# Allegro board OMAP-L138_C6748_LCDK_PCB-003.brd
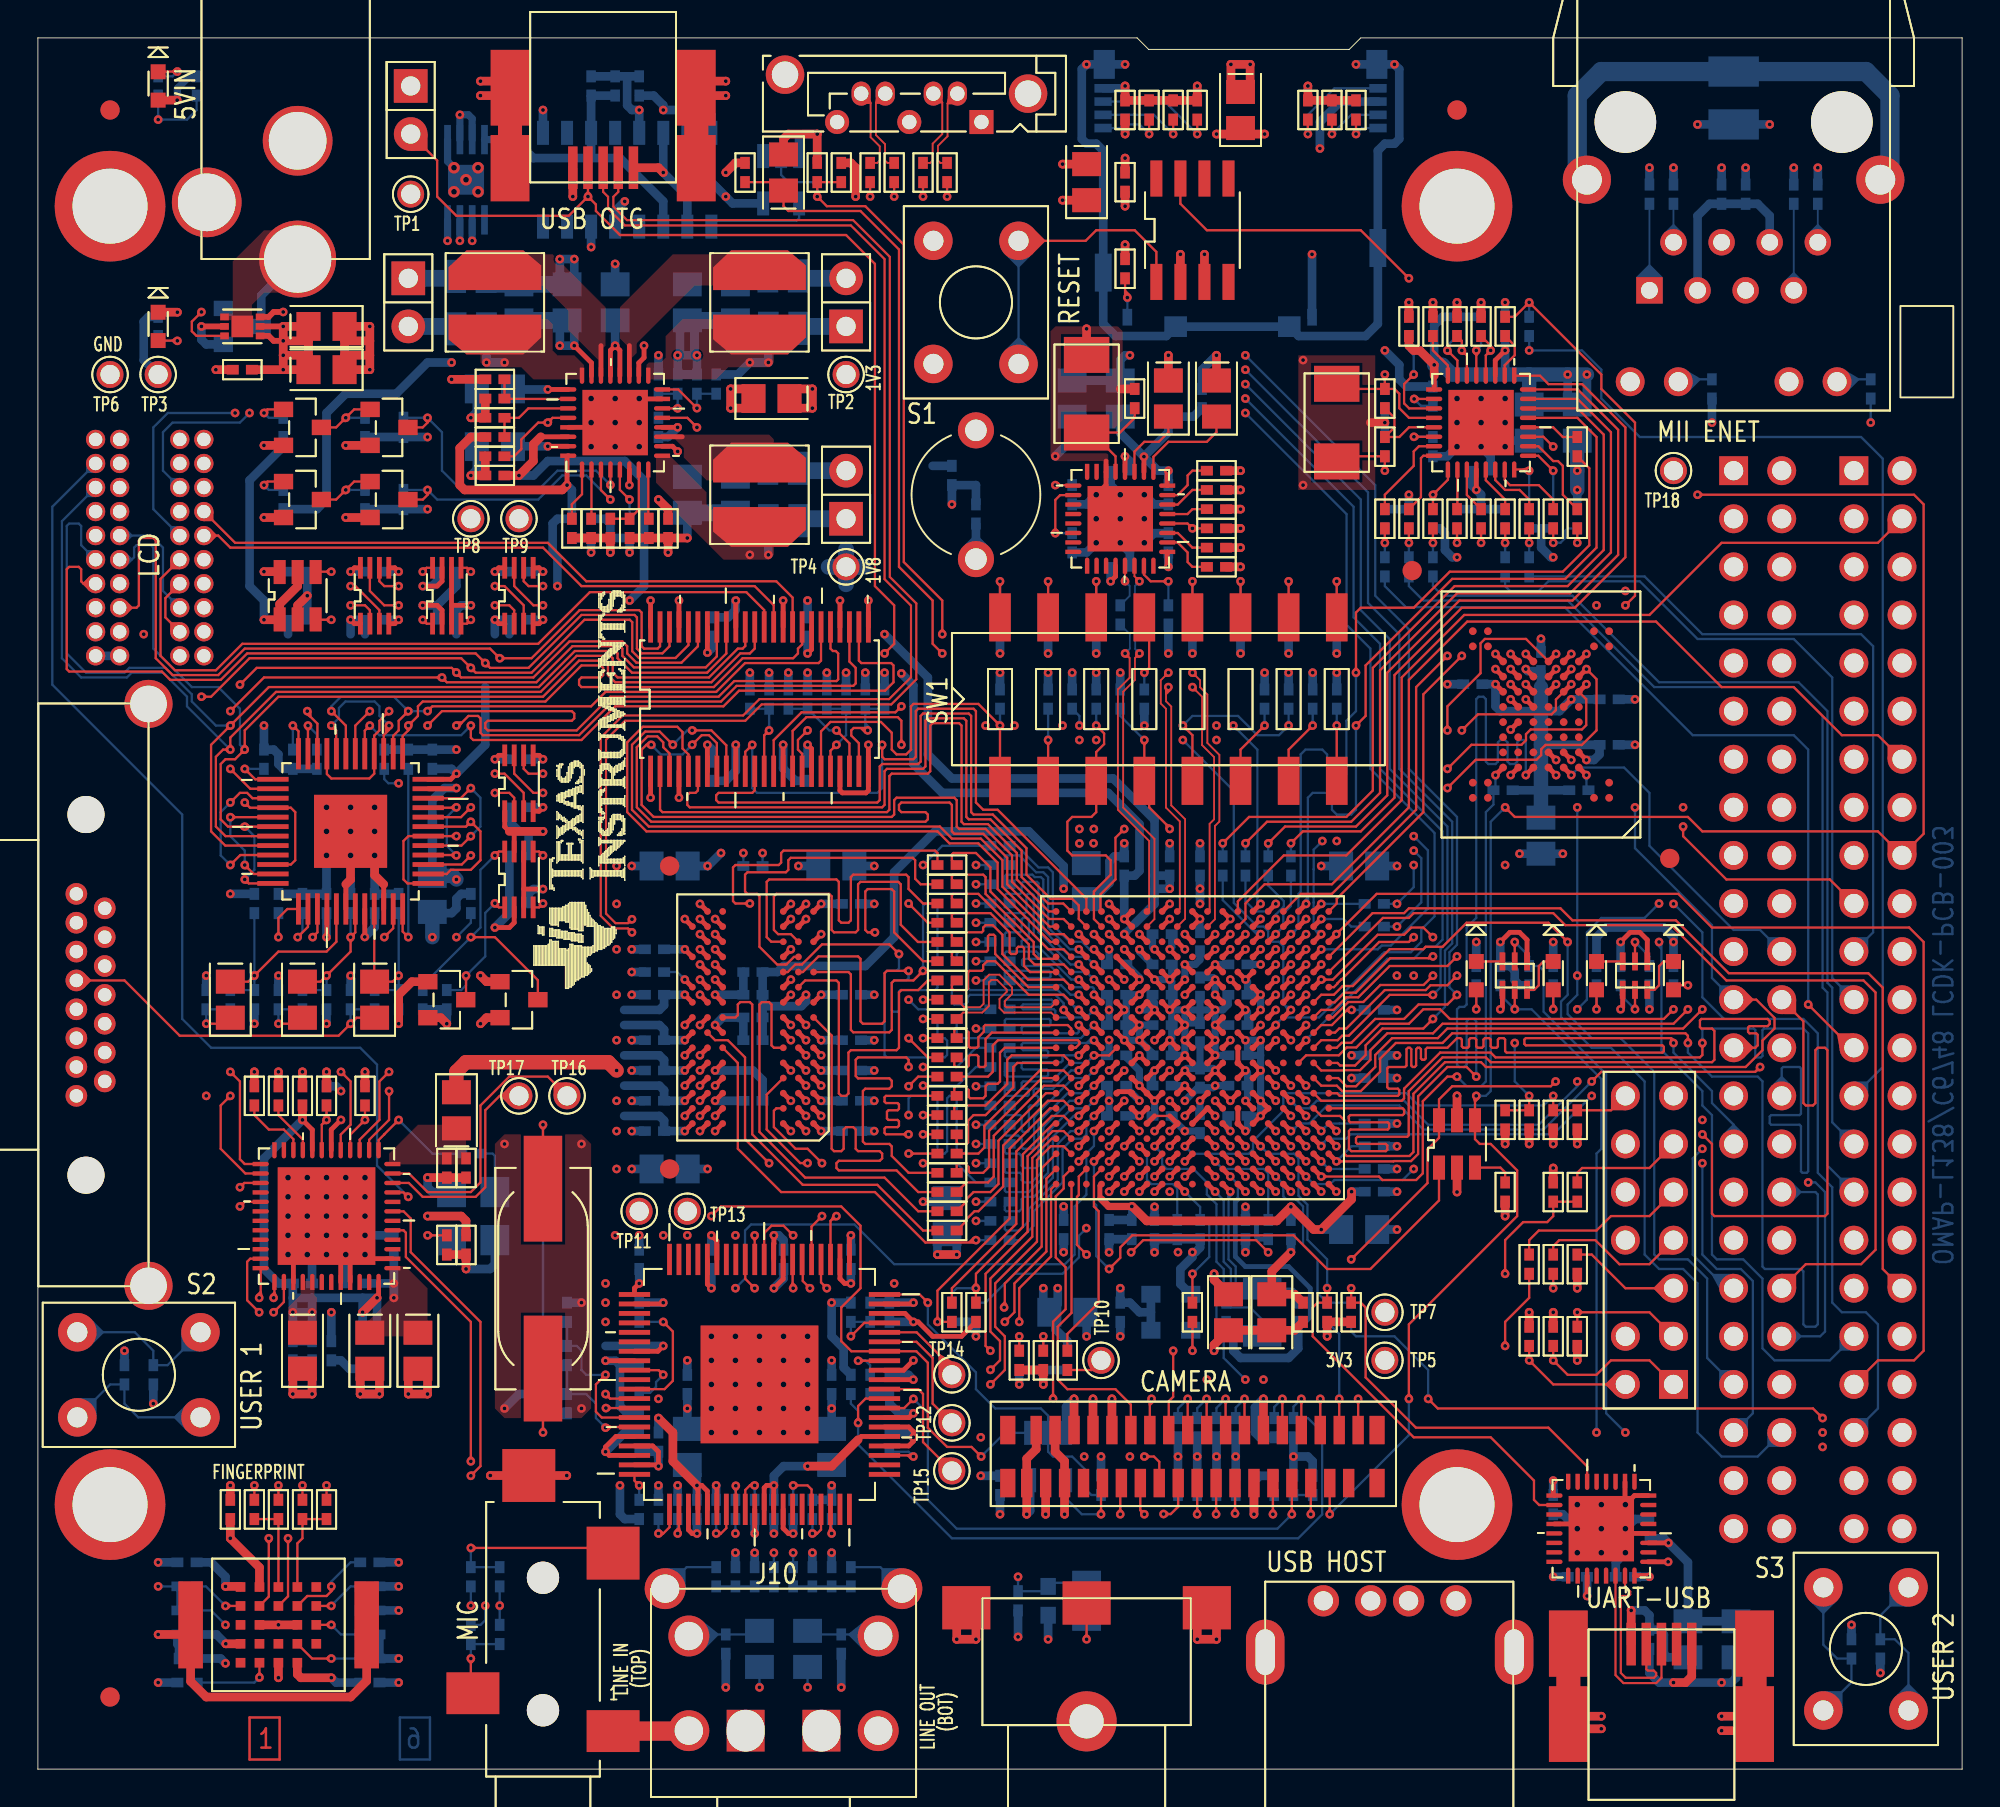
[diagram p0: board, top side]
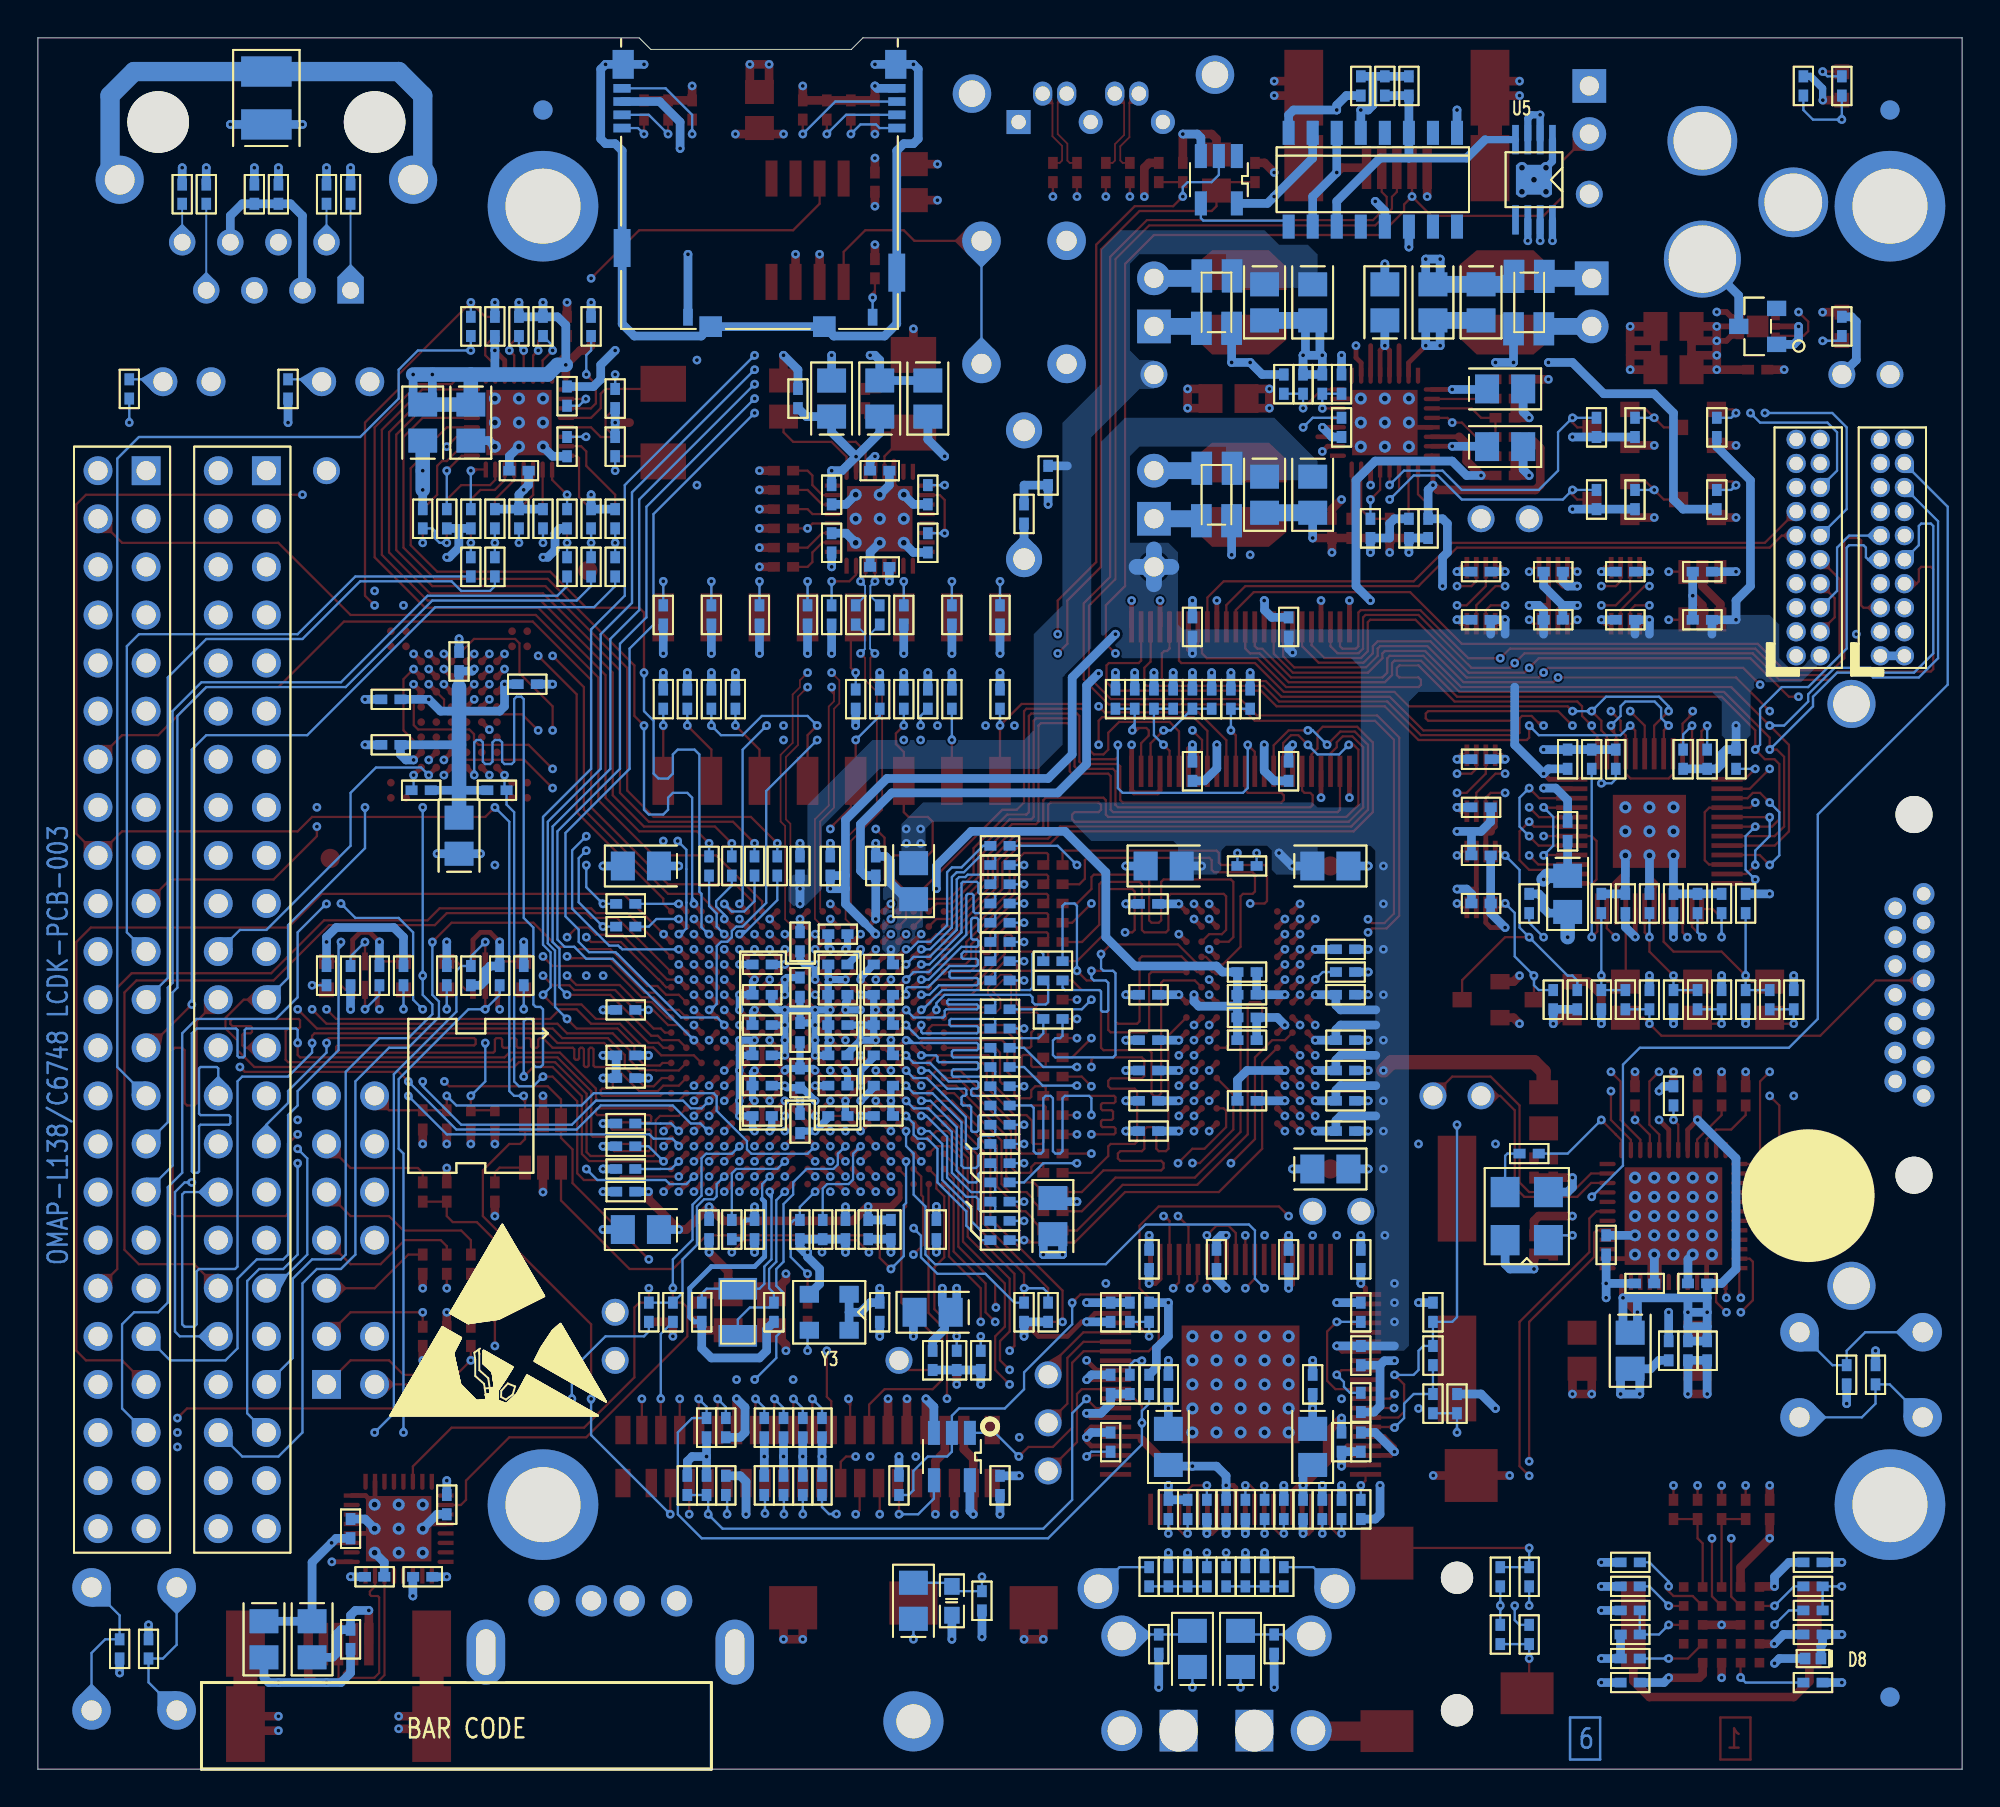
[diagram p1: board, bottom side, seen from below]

Outline 101.6 x 91.44 mm; copper layers: TOP, LYR2_GND, LYR3, LYR4, LYR5_PWR, BOTTOM. Coordinates in mm from the lower left corner of the outline.
Outline path: 0,91.44 0,0 101.6,0 101.6,91.44 69.85,91.44 69.24,90.83 58.65,90.83 58.04,91.44 0,91.44

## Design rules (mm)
net group RX: nets ENET_RXN ENET_RXP
net group SATA_REF_CLK: nets SATA_REF_CLKN SATA_REF_CLKP
net group SATA_REF_CLK_K: nets SATA_REF_CLKN_K SATA_REF_CLKP_K
net group SATA_RX: nets SATA_RXN SATA_RXP
net group SATA_RX_R: nets N27882474 N27882599
net group SATA_TX: nets SATA_TXN SATA_TXP
net group SATA_TX_R: nets N27881562 N27882349
net group TX: nets ENET_TXN ENET_TXP
net group USB0_D: nets USB0_DN USB0_DP
net group USB1_D: nets USB1_DN USB1_DP
net group USBD: nets USB_UART_DN USB_UART_DP
net group 1: nets ACTIVITYLED
net group 2: nets LAN_XTAL1 LAN_XTAL2 VCC_3V3A
net group CVIDEO: nets CVIDEO_DIN0 CVIDEO_DIN1 CVIDEO_DIN2 CVIDEO_DIN3 CVIDEO_DIN4 CVIDEO_DIN5 CVIDEO_DIN6 CVIDEO_DIN7
net group DDR_ADDR: nets DDR_A0 DDR_A1 DDR_A2 DDR_A3 DDR_A4 DDR_A5 DDR_A6 DDR_A7 DDR_A8 DDR_A9 DDR_A10 DDR_A11 DDR_A12 DDR_A13 DDR_BA0 DDR_BA1 DDR_BA2 DDR_CASN DDR_CKE DDR_CLKN DDR_CLKP DDR_CSN DDR_RASN DDR_WEN
net group DDR_ADDR_CPU: nets CPU_DDR_A0 CPU_DDR_A1 CPU_DDR_A2 CPU_DDR_A3 CPU_DDR_A4 CPU_DDR_A5 CPU_DDR_A6 CPU_DDR_A7 CPU_DDR_A8 CPU_DDR_A9 CPU_DDR_A10 CPU_DDR_A11 CPU_DDR_A12 CPU_DDR_A13 CPU_DDR_BA0 CPU_DDR_BA1 CPU_DDR_BA2 CPU_DDR_CASN CPU_DDR_CKE CPU_DDR_CLKN CPU_DDR_CLKP CPU_DDR_CSN CPU_DDR_RASN CPU_DDR_WEN
net group DDR_DATA: nets DDR_DQ0 DDR_DQ1 DDR_DQ2 DDR_DQ3 DDR_DQ4 DDR_DQ5 DDR_DQ6 DDR_DQ7 DDR_DQ8 DDR_DQ9 DDR_DQ10 DDR_DQ11 DDR_DQ12 DDR_DQ13 DDR_DQ14 DDR_DQ15 DDR_DQM0 DDR_DQM1 DDR_DQS0 DDR_DQS1
net group DDR_DATA_CPU: nets CPU_DDR_DQ0 CPU_DDR_DQ1 CPU_DDR_DQ2 CPU_DDR_DQ3 CPU_DDR_DQ4 CPU_DDR_DQ5 CPU_DDR_DQ6 CPU_DDR_DQ7 CPU_DDR_DQ8 CPU_DDR_DQ9 CPU_DDR_DQ10 CPU_DDR_DQ11 CPU_DDR_DQ12 CPU_DDR_DQ13 CPU_DDR_DQ14 CPU_DDR_DQ15 CPU_DDR_DQM0 CPU_DDR_DQM1 CPU_DDR_DQS0 CPU_DDR_DQS1
net group DOUT_LCD_D: nets VPIF_DOUT0/LCD_D_0 VPIF_DOUT1/LCD_D_1 VPIF_DOUT2/LCD_D_2 VPIF_DOUT3/LCD_D_3 VPIF_DOUT4/LCD_D_4 VPIF_DOUT5/LCD_D_5 VPIF_DOUT6/LCD_D_6 VPIF_DOUT7/LCD_D_7 VPIF_DOUT8/LCD_D_8 VPIF_DOUT9/LCD_D_9 VPIF_DOUT10/LCD_D_10 VPIF_DOUT11/LCD_D_11 VPIF_DOUT12/LCD_D_12 VPIF_DOUT13/LCD_D_13 VPIF_DOUT14/LCD_D_14 VPIF_DOUT15/LCD_D_15
net group EMA_A: nets EMA_A0 EMA_A1 EMA_A2 EMA_A3 EMA_A4 EMA_A5 EMA_A6 EMA_A7 EMA_A8 EMA_A9 EMA_A10 EMA_A11 EMA_A12 EMA_BA_0 EMA_BA_1 EMA_CLK EMA_CSN_2 EMA_CSN_3 EMA_CSN_4 EMA_CSN_5
net group EMA_D: nets EMA_D0 EMA_D1 EMA_D2 EMA_D3 EMA_D4 EMA_D5 EMA_D6 EMA_D7 EMA_D8 EMA_D9 EMA_D10 EMA_D11 EMA_D12 EMA_D13 EMA_D14 EMA_D15
net group LCD_D: nets LCD_1V8_D_0 LCD_1V8_D_1 LCD_1V8_D_2 LCD_1V8_D_3 LCD_1V8_D_4 LCD_1V8_D_5 LCD_1V8_D_6 LCD_1V8_D_7 LCD_1V8_D_8 LCD_1V8_D_9 LCD_1V8_D_10 LCD_1V8_D_11 LCD_1V8_D_12 LCD_1V8_D_13 LCD_1V8_D_14 LCD_1V8_D_15
net group MII: nets AXR0/ECAP0_APWM0/MII_TXD0 AXR1/MII_TXD1 AXR2/MII_TXD2 AXR3/MII_TXD3 AXR4/MII_COL AXR5/MII_TXCLK AXR6/MII_TXEN
net group MMCSD0: nets MMCSD0_CLK MMCSD0_CMD MMCSD0_D0 MMCSD0_D1 MMCSD0_D2 MMCSD0_D3 MMCSD0_D4 MMCSD0_D6 MMCSD0_D7

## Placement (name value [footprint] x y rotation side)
BH1  BATTERY Hl, DNI  [BATTERY]  49.53 67.31 90 top
C1  10uF/16V X5R  [0805]  15.24 76.2 0 top
C2  10uF/16V X5R  [0805]  15.24 73.91 0 top
C3  0.1uF/50V X7R  [0402]  10.79 73.91 180 top
C4  0.1uF/50V X7R  [0402]  57.4 83.82 270 top
C5  10uF/16V X5R  [0805]  36.83 67.31 270 bottom
C6  10uF/16V X5R  [0805]  34.29 67.31 270 bottom
C7  1uF/16V X7R  [0402]  33.27 65.53 270 top
C8  10uF/16V X5R  [0805]  24.13 69.85 180 bottom
C9  10uF/16V X5R  [0805]  24.13 72.9 180 bottom
C10  10uF/16V X5R  [0805]  30.48 77.47 90 bottom
C11  10uF/16V X5R  [0805]  34.29 77.47 270 bottom
C12  10uF/16V X5R  [0805]  36.83 77.47 270 bottom
C13  10uF/16V X5R  [0805]  27.94 77.47 270 bottom
C14  10uF/16V X5R  [0805]  25.4 77.47 270 bottom
C15  2.2uF/16V X7R  [0402]  24.13 69.34 180 top
C16  2.2uF/16V X7R  [0402]  24.13 68.33 0 top
C17  2.2uF/16V X7R  [0402]  28.19 65.53 270 bottom
C18  1uF/16V X7R  [0402]  29.21 65.53 270 bottom
C19  0.1uF/50V X7R  [0402]  30.48 88.9 90 bottom
C20  0.1uF/50V X7R  [0402]  80.01 13.97 270 bottom
C21  0.1uF/50V X7R  [0402]  83.82 10.16 180 bottom
C22  10uF/16V X5R  [0805]  89.66 6.86 270 bottom
C23  0.1uF/50V X7R  [0402]  85.09 12.7 90 bottom
C24  0.1uF/50V X7R  [0402]  85.09 6.86 270 bottom
C25  0.22uF/50V X7R  [0402]  60.16 28.5 270 bottom
C26  0.22uF/50V X7R  [0402]  54.61 56.52 90 bottom
C27  0.1uF/50V X7R  [0402]  59.69 67.31 270 bottom
C28  0.1uF/50V X7R  [0402]  59.69 64.77 90 bottom
C29  0.1uF/50V X7R  [0402]  61.47 72.39 90 bottom
C30  10uF/16V X5R  [0805]  59.69 72.39 90 bottom
C31  0.1uF/50V X7R  [0402]  57.15 68.58 180 bottom
C32  0.1uF/50V X7R  [0402]  57.15 63.5 0 bottom
C33  10uF/16V X5R  [0805]  54.61 72.39 270 bottom
C34  0.01uF/50V X7R  [0402]  58.42 60.96 270 bottom
C35  0.1uF/50V X7R  [0402]  56.96 40.9 180 bottom
C36  0.1uF/50V X7R  [0402]  56.96 36.1 180 bottom
C37  0.1uF/50V X7R  [0402]  56.96 39.3 180 bottom
C38  0.1uF/50V X7R  [0402]  59.36 39.3 0 bottom
C39  0.1uF/50V X7R  [0402]  59.36 37.7 0 bottom
C40  0.1uF/50V X7R  [0402]  61.36 43.7 90 bottom
C41  0.1uF/50V X7R  [0402]  61.36 34.1 270 bottom
C42  0.1uF/50V X7R  [0402]  54.36 21.59 270 bottom
C43  0.1uF/50V X7R  [0402]  54.16 28.5 90 bottom
C44  0.1uF/50V X7R  [0402]  63.36 36.1 180 bottom
C45  10uF/16V X5R  [0805]  54.36 24.13 0 bottom
C46  0.01uF/50V X7R  [0402]  57.15 60.96 270 bottom
C47  10pF/50V NPO  [0402]  57.91 72.39 90 top
C48  10uF/16V X5R  [0805]  62.23 72.39 270 top
C49  10uF/16V X5R  [0805]  59.69 72.39 270 top
C50  0.1uF/50V X7R  [0402]  63.76 28.5 270 bottom
C51  0.1uF/50V X7R  [0402]  56.96 42.5 180 bottom
C52  0.1uF/50V X7R  [0402]  56.96 37.7 180 bottom
C53  0.1uF/50V X7R  [0402]  59.36 36.1 180 bottom
C54  0.1uF/50V X7R  [0402]  58.96 28.5 270 bottom
C55  0.1uF/50V X7R  [0402]  59.36 34.5 0 bottom
C56  0.1uF/50V X7R  [0402]  70.56 36.5 0 bottom
C57  0.1uF/50V X7R  [0402]  63.36 40.9 180 bottom
C58  0.1uF/50V X7R  [0402]  63.36 42.5 0 bottom
C59  0.1uF/50V X7R  [0402]  59.36 44.1 180 bottom
C60  0.1uF/50V X7R  [0402]  70.56 37.7 0 bottom
C61  0.1uF/50V X7R  [0402]  63.36 34.5 180 bottom
C62  0.1uF/50V X7R  [0402]  63.36 37.7 180 bottom
C63  10uF/16V X5R  [0805]  69.76 47.7 0 bottom
C64  0.1uF/50V X7R  [0402]  59.76 47.7 90 bottom
C65  0.1uF/50V X7R  [0402]  56.96 34.5 180 bottom
C66  0.1uF/50V X7R  [0402]  66.8 24.13 90 top
C67  0.1uF/50V X7R  [0402]  59.36 42.5 0 bottom
C68  0.1uF/50V X7R  [0402]  57.36 47.7 90 bottom
C69  10uF/16V X5R  [0805]  65.15 24.13 90 top
C70  0.1uF/50V X7R  [0402]  56.56 28.5 270 bottom
C71  0.1uF/50V X7R  [0402]  66.16 28.5 270 bottom
C72  0.1uF/50V X7R  [0402]  61.36 47.7 90 bottom
C73  0.1uF/50V X7R  [0402]  57.76 28.5 270 bottom
C74  0.1uF/50V X7R  [0402]  61.36 41.3 270 bottom
C75  0.1uF/50V X7R  [0402]  61.36 38.9 90 bottom
C76  0.1uF/50V X7R  [0402]  70.56 30.5 0 bottom
C77  0.1uF/50V X7R  [0402]  61.36 36.5 270 bottom
C78  0.1uF/50V X7R  [0402]  63.36 39.3 180 bottom
C79  0.1uF/50V X7R  [0402]  59.36 40.9 0 bottom
C80  10uF/16V X5R  [0805]  69.76 28.5 0 bottom
C81  10uF/16V X5R  [0805]  55.37 83.82 270 top
C82  0.1uF/50V X7R  [0402]  57.4 87.63 270 top
C83  10uF/16V X5R  [0805]  39.37 84.33 90 top
C84  22pF/50V NPO  [0402]  66.55 24.13 270 bottom
C85  22pF/50V NPO  [0402]  62.74 24.13 270 bottom
C86  0.1uF/50V X7R  [0402]  57.15 24.13 270 bottom
C90  0.01uF/50V X7R  [0402]  46.74 84.33 90 top
C91  0.01uF/50V X7R  [0402]  48.01 84.33 90 top
C92  0.01uF/50V X7R  [0402]  45.21 84.33 90 top
C93  0.01uF/50V X7R  [0402]  43.94 84.33 90 top
C94  0.1uF/50V X7R  [0402]  17.78 60.71 0 bottom
C95  0.1uF/50V X7R  [0402]  17.78 63.25 180 bottom
C96  0.1uF/50V X7R  [0402]  20.83 49.53 270 bottom
C97  0.1uF/50V X7R  [0402]  17.78 45.72 270 bottom
C98  1uF/16V X7R  [0402]  15.24 45.72 90 bottom
C99  0.1uF/50V X7R  [0402]  35.56 52.7 90 bottom
C100  0.1uF/50V X7R  [0402]  40.64 52.7 90 bottom
C101  0.1uF/50V X7R  [0402]  35.56 60.33 270 bottom
C102  0.1uF/50V X7R  [0402]  40.64 60.33 270 bottom
C103  0.1uF/50V X7R  [0402]  20.83 53.34 270 bottom
C104  0.1uF/50V X7R  [0402]  25.4 50.8 0 bottom
C105  33pF/50V NPO  [0402]  10.16 40.64 90 bottom
C106  0.1uF/50V X7R  [0402]  25.4 53.34 180 bottom
C107  0.1uF/50V X7R  [0402]  22.86 45.72 270 bottom
C108  100pF/50V NPO  [0402]  11.43 40.64 90 bottom
C109  270pF/50V NPO  [0402]  8.89 40.64 270 bottom
C110  33pF/50V NPO  [0402]  13.97 40.64 90 bottom
C111  100pF/50V NPO  [0402]  15.24 40.64 90 bottom
C112  270pF/50V NPO  [0402]  12.7 40.64 270 bottom
C113  33pF/50V NPO  [0402]  17.78 40.64 90 bottom
C114  100pF/50V NPO  [0402]  19.05 40.64 90 bottom
C115  270pF/50V NPO  [0402]  16.51 40.64 270 bottom
C116  0.1uF/50V X7R  [0402]  12.7 45.72 270 bottom
C118  0.1uF/50V X7R  [0402]  25.4 45.72 180 bottom
C119  0.1uF/50V X7R  [0402]  37.76 39.7 180 bottom
C120  0.01uF/50V X7R  [0402]  32.56 43.3 180 bottom
C121  0.1uF/50V X7R  [0402]  32.56 40.9 180 bottom
C122  0.01uF/50V X7R  [0402]  32.56 38.5 180 bottom
C123  10uF/16V X5R  [0805]  33.36 31.7 180 bottom
C124  10uF/16V X5R  [0805]  33.36 47.7 180 bottom
C125  0.1uF/50V X7R  [0402]  32.56 36.9 180 bottom
C126  0.01uF/50V X7R  [0402]  32.56 35.3 180 bottom
C127  0.1uF/50V X7R  [0402]  32.56 33.7 180 bottom
C128  0.01uF/50V X7R  [0402]  42.96 45.7 0 bottom
C129  0.1uF/50V X7R  [0402]  42.96 40.9 0 bottom
C130  0.01uF/50V X7R  [0402]  42.96 38.5 0 bottom
C131  10uF/16V X5R  [0805]  42.16 47.7 0 bottom
C132  0.1uF/50V X7R  [0402]  42.96 36.9 0 bottom
C133  0.01uF/50V X7R  [0402]  42.96 35.3 0 bottom
C134  0.1uF/50V X7R  [0402]  42.96 33.7 0 bottom
C135  0.01uF/50V X7R  [0402]  37.76 35.3 0 bottom
C136  0.1uF/50V X7R  [0402]  37.76 42.1 0 bottom
C137  10pF, DNI  [0402]  92.71 83.19 90 bottom
C138  0.1uF/50V X7R  [0402]  75.76 57.3 180 bottom
C139  0.1uF/50V X7R  [0402]  79.36 58.5 90 bottom
C140  0.01uF/50V X7R  [0402]  82.96 54.1 0 bottom
C141  0.1uF/50V X7R  [0402]  25.4 48.26 180 bottom
C142  22pF/50V NPO  [0402]  27.94 24.13 90 bottom
C143  22pF/50V NPO  [0402]  26.67 19.3 90 bottom
C144  1uF/16V X7R  [0402]  73.66 69.85 270 bottom
C145  1uF/16V X7R  [0402]  82.96 56.5 0 bottom
C146  0.1uF/50V X7R  [0402]  34.29 20.32 90 bottom
C147  0.1uF/50V X7R  [0402]  32.77 17.27 270 bottom
C148  0.1uF/50V X7R  [0402]  34.8 13.72 270 bottom
C149  0.1uF/50V X7R  [0402]  31.75 26.92 90 bottom
C150  0.1uF/50V X7R  [0402]  39.37 26.92 90 bottom
C151  0.1uF/50V X7R  [0402]  44.96 24.13 90 bottom
C152  0.1uF/50V X7R  [0402]  35.56 26.92 270 bottom
C153  0.1uF/50V X7R  [0402]  42.93 26.92 270 bottom
C154  0.1uF/50V X7R  [0402]  31.75 21.84 270 bottom
C155  0.1uF/50V X7R  [0402]  44.96 20.32 270 bottom
C156  0.1uF/50V X7R  [0402]  41.91 20.32 90 bottom
C157  0.1uF/50V X7R  [0402]  31.75 17.27 270 bottom
C158  0.1uF/50V X7R  [0402]  38.86 13.72 270 bottom
C159  0.1uF/50V X7R  [0402]  31.75 13.72 270 bottom
C160  0.1uF/50V X7R  [0402]  32.77 13.72 90 bottom
C161  0.1uF/50V X7R  [0402]  33.78 13.72 90 bottom
C162  0.1uF/50V X7R  [0402]  36.83 13.72 90 bottom
C163  330pF/100V X7R  [0603]  53.34 8.89 270 bottom
C164  0.1uF/50V X7R  [0402]  35.81 13.72 90 bottom
C165  0.1uF/50V X7R  [0402]  37.85 13.72 270 bottom
C166  0.1uF/50V X7R  [0402]  39.88 13.72 270 bottom
C167  0.1uF/50V X7R  [0402]  40.89 13.72 90 bottom
C168  0.1uF/50V X7R  [0402]  41.91 13.72 90 bottom
C169  0.1uF/50V X7R  [0402]  44.96 17.27 90 bottom
C170  10uF/16V X5R  [0805]  55.36 46.9 270 bottom
C171  10uF/16V X5R  [0805]  48.01 29.21 90 bottom
C172  0.1uF/50V X7R  [0402]  38.86 10.16 90 bottom
C173  0.47uF/50V X7R  [0402]  22.86 7.11 270 bottom
C174  220pF/50V NPO  [0402]  37.85 10.16 270 bottom
C175  0.47uF/50V X7R  [0402]  22.86 10.16 90 bottom
C176  0.1uF/50V X7R  [0402]  39.88 10.16 90 bottom
C177  220pF/50V NPO  [0402]  40.89 10.16 270 bottom
C178  10uF/16V X5R  [0805]  40.64 6.35 90 bottom
C179  10uF/16V X5R  [0805]  38.1 6.35 90 bottom
C180  0.1uF/50V X7R  [0402]  22.61 27.69 90 top
C181  1uF/16V X7R  [0402]  21.59 31.75 270 top
C182  0.1uF/50V X7R  [0402]  18.8 27.69 90 bottom
C183  0.1uF/50V X7R  [0402]  16.76 25.65 180 bottom
C184  10uF/16V X5R  [0805]  20.07 22.1 270 top
C185  0.1uF/50V X7R  [0402]  15.49 22.1 90 bottom
C186  0.1uF/50V X7R  [0402]  22.61 31.75 270 top
C187  0.1uF/50V X7R  [0402]  13.97 25.65 0 bottom
C188  0.1uF/50V X7R  [0402]  14.48 22.1 270 bottom
C189  0.1uF/50V X7R  [0402]  13.46 22.1 270 bottom
C190  0.1uF/50V X7R  [0402]  13.97 35.56 90 top
C191  10uF/16V X5R  [0805]  13.97 22.1 270 top
C193  0.1uF/50V X7R  [0402]  76.2 68.58 0 bottom
C194  10pF, DNI  [0402]  93.98 83.19 90 bottom
C196  10pF, DNI  [0402]  86.36 83.19 90 bottom
C197  10pF, DNI  [0402]  85.09 83.19 90 bottom
C198  0.022uF,10V  [0402]  90.17 83.19 90 bottom
C199  10uF/16V X5R  [0805]  78.74 71.12 270 bottom
C200  0.1uF/50V X7R  [0402]  77.47 76.2 90 bottom
C201  0.1uF/50V X7R  [0402]  72.39 76.2 90 top
C202  33pF/50V NPO  [0402]  71.12 69.85 270 bottom
C203  33pF/50V NPO  [0402]  71.12 72.39 90 bottom
C204  0.1uF/50V X7R  [0402]  25.4 60.71 0 bottom
C205  0.1uF/50V X7R  [0402]  25.4 63.25 180 bottom
C206  0.1uF/50V X7R  [0402]  21.59 63.25 180 bottom
C207  0.47uF/50V X7R  [0402]  10.16 13.72 270 top
C208  0.47uF/50V X7R  [0402]  17.53 4.57 180 bottom
C209  0.47uF/50V X7R  [0402]  7.87 10.92 0 bottom
C210  0.1uF/50V X7R  [0402]  21.59 60.71 180 bottom
C211  0.47uF/50V X7R  [0402]  17.53 9.65 180 bottom
C212  0.47uF/50V X7R  [0402]  17.53 10.92 180 bottom
C213  0.47uF/50V X7R  [0402]  17.53 5.84 180 bottom
C214  0.47uF/50V X7R  [0402]  7.87 4.57 0 bottom
C215  0.1uF/50V X7R  [0402]  50.8 14.99 90 bottom
C216  0.1uF/50V X7R  [0402]  13.72 60.71 180 bottom
C217  0.1uF/50V X7R  [0402]  13.72 63.25 0 bottom
D1  BZX84B5V1LT1G  [SOT23_3]  10.79 76.2 90 bottom
D2  LED  [LED2-31SQ]  6.35 88.9 270 top
D3  LED  [LED2-31SQ]  6.35 76.2 270 top
D4  LED  [LED2-31SQ]  75.95 41.91 270 top
D5  LED  [LED2-31SQ]  80.01 41.91 270 top
D6  LED  [LED2-31SQ]  82.3 41.91 270 top
D7  LED  [LED2-31SQ]  86.36 41.91 270 top
D8  CP64004T  [DO1006]  7.87 5.84 180 bottom
DN1  BAV99LT1  [SOT23_3]  21.59 40.64 270 top
DN2  BAV99LT1  [SOT23_3]  25.4 40.64 270 top
FB1  MMZ2012S121A  [0805]  38.73 72.39 180 top
FB2  MMZ2012S121A  [0805]  87.12 6.86 270 bottom
FB3  MMZ2012S121A  [0805]  57.15 72.39 90 bottom
FB4  MMZ2012S121A  [0805]  62.87 24.13 90 top
FB5  MMZ2012S121A  [0805]  63.5 87.63 270 top
FB6  MMZ2012S121A  [0805]  20.83 46.23 270 bottom
FB8  MMZ2012S121A  [0805]  79.36 49.3 90 bottom
FB9  MMZ2012S121A  [0805]  34.29 17.02 270 bottom
FB10  MMZ2012S121A  [0805]  41.91 17.02 270 bottom
FB11  MMZ2012S121A  [0805]  55.37 8.89 90 bottom
FB14  MMZ2012S121A  [0805]  17.53 22.1 270 top
FB15  MMZ2012S121A  [0805]  22.1 34.8 90 top
FB16  MMZ2012S121A  [0805]  17.53 22.1 270 bottom
FB18  MMZ2012S121A  [0805]  81.28 71.12 90 bottom
J1  Power Jack RAPC712  [RAPC712]  13.72 79.76 270 top
J2  56579-0576  [USB5MINI_4SHIELDED_SMD-4]  29.84 84.58 270 top
J3  56579-0576  [USB5MINI_4SHIELDED_SMD-4]  85.72 6.6 90 top
J4  SCHA5B0200  [SD-MICRO-SCHA5B0300]  63.5 86.68 0 bottom
J5  USB-A Conn. - 87520-xx1xx  [USB_A_SH]  67.87 8.89 0 top
J6  72454-014LF  [CON2X100P-14_V6]  85.09 27.94 90 top
J7  SD-67491-002  [SATA]  41.91 87 0 top
J8  070213FR  [DB15F_60-59LS]  2.54 40.89 90 top
J9  RCJ-014  [RCA4SMD_11X15MM]  55.37 2.52 180 top
J10  SJD-3510-33  [JACK6_551X433_STACK]  39.37 2.03 180 top
J11  STX-3500-4NTR  [STX3500]  26.67 6.86 90 top
J13  ETHER  [RJ45-2LED]  85.09 78.11 90 top
J14  CONN_PCB_23x2-S  [HEADER23X2]  89.53 68.58 270 top
J15  CONN_PCB_23x2-S  [HEADER23X2]  95.89 68.58 270 top
J16  52559-3652  [CON36UPSMD_P5MM]  60.96 16.51 180 top
JP1  HEADER 2  [HEADER_2X1]  19.68 88.9 180 top
JP2  HEADER 2  [HEADER_2X1]  42.67 66.04 0 top
JP3  HEADER 2  [HEADER_2X1]  19.56 78.74 180 top
JP4  HEADER 2  [HEADER_2X1]  42.67 76.2 0 top
L1  2.2uH/1.7A  [IND3P4SMD_5SQ]  38.1 67.31 270 top
L2  3.3uH/2.6A  [IND3P4SMD_5SQ]  24.13 77.47 90 top
L3  2.2uH/1.7A  [IND3P4SMD_5SQ]  38.1 77.47 270 top
L4  1uH/80mA  [0805]  10.16 40.64 270 top
L5  1uH/80mA  [0805]  13.97 40.64 270 top
L6  1uH/80mA  [0805]  17.78 40.64 270 top
NOREF  -  []  0 0 0 top
NOREF#2  -  []  0 0 0 top
NOREF#3  -  []  74.93 13.97 0 top
NOREF#4  -  []  69.85 91.44 0 top
NOREF#5  -  []  0 -15.09 0 top
NOREF#6  -  []  -303.34 -250.06 0 top
NOREF#7  -  []  -14.07 0 90 top
NOREF#8  -  []  3.81 82.55 0 top
NOREF#9  -  [unnamed#2]  74.93 87.63 0 top
NOREF#10  -  []  0 91.44 0 top
NOREF#11  -  [unnamed#2]  3.81 3.81 0 top
NOREF#12  -  [unnamed#2]  3.81 82.55 0 top
NOREF#13  -  [unnamed#2]  74.93 13.97 0 top
NOREF#14  -  []  3.81 13.97 0 top
NOREF#15  -  [unnamed#2]  3.81 87.63 0 top
NOREF#16  -  [unnamed#2]  3.81 13.97 0 top
NOREF#17  -  []  3.81 13.97 0 top
NOREF#18  -  []  58.65 90.83 0 top
NOREF#19  -  []  101.6 0 0 top
NOREF#20  -  []  58.65 90.83 0 top
NOREF#21  -  []  58.04 91.44 0 top
NOREF#22  -  [unnamed#2]  74.93 82.55 0 top
NOREF#23  -  []  69.24 90.83 0 top
NOREF#24  -  []  70.11 26.07 180 bottom
NOREF#25  -  [unnamed#2]  74.93 87.63 180 bottom
NOREF#26  -  [unnamed#2]  3.81 87.63 180 bottom
NOREF#27  -  [unnamed#2]  3.81 3.81 180 bottom
NOREF#28  -  []  87.12 3.05 180 bottom
P1  HEADER_10X2  [CONN2X10_4028]  4.32 58.8 90 top
P2  HEADER_10X2  [CONN2X10_4028]  8.76 58.8 90 top
Q1  MMBT3904LT1G  [SOT23_3]  18.54 67.06 270 top
Q2  MMBT3904LT1G  [SOT23_3]  18.54 70.87 270 top
Q3  MMBT3904LT1G  [SOT23_3]  13.97 67.06 270 top
Q4  MMBT3904LT1G  [SOT23_3]  13.97 70.87 270 top
Q5  DMC56404  [SMINI6-F3-B]  84.33 41.91 180 top
Q6  DMC56404  [SMINI6-F3-B]  77.98 41.91 180 top
R1  510E/5% 1/10W  [0402]  6.35 88.9 90 bottom
R2  0.05ohm1% Sense  [1206_4PIN]  39.37 67.31 90 bottom
R3  1E/5%/1/10W  [0402]  32.77 70.87 90 bottom
R4  0.05ohm1% Sense  [1206_4PIN]  22.86 77.47 270 bottom
R5  0.05ohm1% Sense  [1206_4PIN]  39.37 77.47 90 bottom
R6  576K/1% 1/10W  [0402]  35.81 73.15 90 bottom
R7  4.7K/5% 1/10W  [0402]  32.26 65.53 270 top
R8  499K/1% 1/10W  [0402]  34.8 73.15 90 bottom
R9  330E/1% 1/10W  [0402]  6.35 76.2 270 bottom
R10  4.7K/5% 1/10W  [0402]  29.21 65.53 270 top
R11  4.7K/5% 1/10W  [0402]  28.19 65.53 270 top
R12  5.6K/1% 1/10W  [0402]  32.77 73.15 90 bottom
R13  0E  [0402]  30.23 65.53 270 top
R14  1.4K/1% 1/10W  [0402]  33.78 73.15 270 bottom
R15  4.7K/5% 1/10W  [0402]  31.24 65.53 90 bottom
R16  OR, DNI  [0402]  31.24 65.53 90 top
R17  200K/1% 1/10W  [0402]  24.13 72.39 0 top
R18  160K/1% 1/10W  [0402]  24.13 73.41 180 top
R19  300K/1% 1/10W  [0402]  24.13 71.37 0 top
R20  60K/1% 1/10W  [0402]  24.13 70.36 0 top
R21  4.7K/5% 1/10W  [0402]  31.75 88.9 90 bottom
R22  4.7K/5% 1/10W  [0402]  19.3 67.06 270 bottom
R23  4.7K/5% 1/10W  [0402]  19.3 70.87 270 bottom
R24  4.7K/5% 1/10W  [0402]  17.27 67.06 270 bottom
R25  4.7K/5% 1/10W  [0402]  29.21 88.9 90 bottom
R26  4.7K/5% 1/10W  [0402]  17.27 70.87 270 bottom
R27  1K/1% 1/10W  [0402]  12.95 67.06 90 bottom
R28  1K/1% 1/10W  [0402]  12.95 70.87 90 bottom
R29  0E/5% 1/10W  [0402]  48.26 68.33 270 bottom
R30  10K, 5%  [0402]  81.28 10.16 0 bottom
R31  0, DNI  [0402]  49.53 66.29 270 bottom
R33  49.9E/1% 1/10W  [0402]  49.53 24.13 270 bottom
R34  4.7K/5% 1/10W  [0402]  62.23 64.52 180 top
R35  4.7K/5% 1/10W  [0402]  62.23 66.55 180 top
R36  4.7K/5% 1/10W  [0402]  62.23 68.58 180 top
R37  4.7K/5% 1/10W  [0402]  54.61 64.77 270 bottom
R38  4.7K/5% 1/10W  [0402]  54.61 67.31 270 bottom
R39  4.7K/5% 1/10W  [0402]  62.23 67.56 0 top
R40  4.7K/5% 1/10W  [0402]  62.23 63.5 0 top
R41  10K/1% 1/10W  [0402]  62.23 65.53 0 top
R42  10K, DNI  [0402]  59.69 60.96 270 bottom
R43  180, 1%  [0402]  60.96 24.13 90 top
R44  10K/5% 1/10W  [0402]  57.4 79.25 270 top
R45  10K/5% 1/10W  [0402]  58.67 87.63 270 top
R46  10K/5% 1/10W  [0402]  61.21 87.63 270 top
R47  10K/5% 1/10W  [0402]  67.06 87.63 270 top
R48  10K/5% 1/10W  [0402]  68.33 87.63 270 top
R49  10K/5% 1/10W  [0402]  69.6 87.63 270 top
R50  10K/5% 1/10W  [0402]  59.94 87.63 270 top
R51  10K, DNI  [0402]  42.42 84.33 270 top
R52  10K/1% 1/10W  [0402]  41.15 84.33 90 top
R53  0E/5% 1/10W  [0402]  37.76 47.7 180 bottom
R54  0E/5% 1/10W  [0402]  37.34 84.33 90 top
R55  10K/1% 1/10W  [0402]  81.28 22.86 90 top
R57  10K/1% 1/10W  [0402]  80.01 22.86 270 top
R58  10K/1% 1/10W  [0402]  80.01 30.48 270 top
R59  10K/1% 1/10W  [0402]  64.96 28.5 90 bottom
R60  100E/1% 1/10W  [0402]  54.36 21.59 90 top
R61  4.7K  [0402]  78.74 22.86 90 top
R62  4.7K  [0402]  81.28 34.29 90 top
R63  4.7K  [0402]  77.47 34.29 90 top
R64  100E/1% 1/10W  [0402]  81.28 26.67 270 top
R65  10K/1% 1/10W  [0402]  77.47 30.48 90 top
R66  2.2K, DNI  [0402]  80.01 34.29 90 top
R67  2.2K, DNI  [0402]  78.74 34.29 90 top
R73  5.6K/1%  [0402]  53.34 56.52 90 bottom
R74  5.6K/1%  [0402]  55.88 56.52 270 bottom
R75  5.6K/1%  [0402]  50.8 56.52 90 bottom
R76  1K/5% 1/10W  [0402]  50.8 60.96 90 bottom
R77  1K/5% 1/10W  [0402]  53.34 60.96 90 bottom
R78  1K/5% 1/10W  [0402]  55.88 60.96 90 bottom
R79  1K/5% 1/10W  [0402]  58.42 56.52 90 bottom
R80  5.6K/1%  [0402]  57.15 56.52 270 bottom
R81  0E/5% 1/10W  [0402]  48.26 24.13 270 top
R82  1K/5% 1/10W  [0402]  42.67 56.52 270 bottom
R83  1K/5% 1/10W  [0402]  40.64 56.52 270 bottom
R84  1K/5% 1/10W  [0402]  44.7 56.52 270 bottom
R85  1K/5% 1/10W  [0402]  38.61 56.52 270 bottom
R86  10K/1% 1/10W  [0402]  66.29 14.99 270 bottom
R87  330E/5% 1/10W  [0402]  80.01 41.91 90 bottom
R88  330E/5% 1/10W  [0402]  75.95 41.91 90 bottom
R89  10K/1% 1/10W  [0402]  66.29 18.03 90 bottom
R90  100E/1% 1/10W  [0402]  62.56 47.7 90 bottom
R91  100E/1% 1/10W  [0402]  66.16 47.7 90 bottom
R92  100E/1% 1/10W  [0402]  64.96 47.7 90 bottom
R93  100E/1% 1/10W  [0402]  63.76 47.7 90 bottom
R94  33E/5% 1/10W  [0402]  70.56 44.5 0 bottom
R95  33E/5% 1/10W  [0402]  70.56 45.7 0 bottom
R96  10K/1% 1/10W  [0402]  69.34 24.13 90 top
R97  10K/1% 1/10W  [0402]  68.07 24.13 90 top
R98  4.7K/5% 1/10W  [0402]  13.46 53.34 270 bottom
R99  4.7K/5% 1/10W  [0402]  11.94 53.34 90 bottom
R100  4.7K/5% 1/10W  [0402]  14.73 53.34 270 bottom
R101  100K/5%  [0402]  77.22 41.91 270 bottom
R102  100K/5%  [0402]  78.74 41.91 90 bottom
R103  4.7K/5% 1/10W  [0402]  70.56 31.7 180 bottom
R104  4.7K/5% 1/10W  [0402]  70.56 40.1 180 bottom
R105  4.7K/5% 1/10W  [0402]  70.56 34.1 180 bottom
R106  4.7K/5% 1/10W  [0402]  70.56 32.9 180 bottom
R107  10E/1% 1/10W  [0402]  50.8 28.96 0 bottom
R108  10E/1% 1/10W  [0402]  50.8 29.97 0 bottom
R109  10E/1% 1/10W  [0402]  48.01 28.45 0 top
R110  10E/1% 1/10W  [0402]  50.8 32 0 bottom
R111  10E/1% 1/10W  [0402]  48.01 30.48 0 top
R112  10E/1% 1/10W  [0402]  48.01 32.51 0 top
R113  4.7K/5% 1/10W  [0402]  18.29 53.34 90 bottom
R114  4.7K/5% 1/10W  [0402]  19.56 53.34 90 bottom
R115  10E/1% 1/10W  [0402]  48.01 31.5 0 top
R116  10E/1% 1/10W  [0402]  48.01 33.53 0 top
R117  3.4K/1% 1/10W  [0402]  13.97 45.72 90 bottom
R118  75E/5%  1/10W  [0402]  11.43 45.72 270 bottom
R119  75E/5%  1/10W  [0402]  16.51 45.72 270 bottom
R120  2.2K, DNI  [0402]  20.32 40.64 90 bottom
R121  2.2K, DNI  [0402]  21.59 40.64 90 bottom
R122  75E/5%  1/10W  [0402]  19.05 45.72 90 bottom
R123  1K/1% 1/10W  [0402]  37.76 38.5 0 bottom
R124  1K/1% 1/10W  [0402]  37.76 40.9 180 bottom
R125  4.7K/5% 1/10W  [0402]  32.56 42.1 180 bottom
R126  22E/1% 1/10W  [0402]  48.01 38.61 180 top
R127  22E/1% 1/10W  [0402]  50.8 39.12 180 bottom
R128  22E/1% 1/10W  [0402]  48.01 37.59 180 top
R129  22E/1% 1/10W  [0402]  50.8 40.13 180 bottom
R130  22E/1% 1/10W  [0402]  48.01 41.66 180 top
R131  10E/1% 1/10W  [0402]  48.01 39.62 180 top
R132  10E/1% 1/10W  [0402]  48.01 40.64 180 top
R133  22E/1% 1/10W  [0402]  48.01 34.54 180 top
R134  22E/1% 1/10W  [0402]  50.8 27.94 180 bottom
R135  22E/1% 1/10W  [0402]  50.8 36.07 180 bottom
R136  22E/1% 1/10W  [0402]  48.01 29.46 180 top
R137  4.7K/5%  [0402]  77.36 51.7 0 bottom
R138  10E/1% 1/10W  [0402]  50.8 30.99 0 bottom
R139  4.7K/5%  [0402]  81.36 51.7 180 bottom
R140  10E/1% 1/10W  [0402]  50.8 34.04 0 bottom
R141  4.7K/5% 1/10W  [0402]  56.13 14.99 90 bottom
R142  100K/1% 1/10W  [0402]  27.94 21.84 270 bottom
R143  4.7K/5% 1/10W  [0402]  43.94 20.32 90 bottom
R144  0E/5% 1/10W  [0402]  27.94 19.3 90 bottom
R145  4.7K/5% 1/10W  [0402]  31.75 24.13 270 bottom
R146  20K, DNI  [0402]  42.93 20.32 90 bottom
R147  1K, DNI  [0402]  67.31 14.99 270 bottom
R148  4.7K/5% 1/10W  [0402]  42.93 24.13 90 bottom
R149  4.7K, DNI  [0402]  43.94 24.13 270 bottom
R150  2K/5% 1/10W  [0402]  24.38 7.11 270 bottom
R151  2K/5% 1/10W  [0402]  24.38 10.16 90 bottom
R152  0E/5% 1/10W  [0402]  35.81 10.16 90 bottom
R153  5.6K, DNI  [0402]  36.83 10.16 270 bottom
R154  0E/5% 1/10W  [0402]  42.93 10.16 90 bottom
R155  5.6K, DNI  [0402]  41.91 10.16 270 bottom
R156  20K/1% 1/10W  [0402]  42.42 6.6 270 bottom
R157  20K/1% 1/10W  [0402]  36.32 6.6 270 bottom
R158  2K/1% 1/10W  [0402]  11.43 35.56 270 top
R159  2K/1% 1/10W  [0402]  12.7 35.56 270 top
R160  2K, DNI  [0402]  15.24 35.56 90 bottom
R161  20K, DNI  [0402]  17.27 35.56 90 top
R162  2K/1% 1/10W  [0402]  15.24 35.56 270 top
R163  4.7K/5% 1/10W  [0402]  21.59 27.69 90 top
R164  33E/5% 1/10W  [0402]  22.86 32.51 0 bottom
R165  49.9E/1% 1/10W  [0402]  74.93 76.2 270 top
R166  49.9E/1% 1/10W  [0402]  74.93 76.2 270 bottom
R167  49.9E/1% 1/10W  [0402]  76.2 76.2 270 top
R168  49.9E/1% 1/10W  [0402]  76.2 76.2 270 bottom
R169  1.5K/1% 1/10W  [0402]  78.74 66.04 90 bottom
R170  4.7K/5% 1/10W  [0402]  73.66 66.04 270 bottom
R171  1.5K/1% 1/10W  [0402]  80.01 66.04 90 bottom
R172  100E/1% 1/10W  [0402]  72.39 66.04 90 top
R173  100E/1% 1/10W  [0402]  73.66 66.04 90 top
R174  100E/1% 1/10W  [0402]  74.93 66.04 90 top
R175  100E/1% 1/10W  [0402]  76.2 66.04 90 top
R176  330/5% 1/10W  [0402]  88.39 72.9 90 bottom
R177  100E/1% 1/10W  [0402]  77.47 76.2 270 top
R178  100E/1% 1/10W  [0402]  71.12 66.04 90 top
R179  100E/1% 1/10W  [0402]  77.47 66.04 90 top
R180  0,1210  [1210]  89.54 88.27 90 bottom
R181  330/5% 1/10W  [0402]  96.77 72.9 90 bottom
R182  100E/1% 1/10W  [0402]  81.28 69.85 90 top
R183  100E/1% 1/10W  [0402]  80.01 66.04 90 top
R184  100E/1% 1/10W  [0402]  78.74 66.04 90 top
R185  10E/5% 1/10W  [0402]  88.9 83.19 90 bottom
R186  12.1K/1% 1/10W  [0402]  73.66 76.2 90 top
R187  0E/5% 1/10W  [0402]  81.28 66.04 90 top
R188  4.7K/5% 1/10W  [0402]  72.39 76.2 90 bottom
R189  4.7K/5% 1/10W  [0402]  73.66 72.52 90 bottom
R190  10E/1% 1/10W  [0402]  71.12 69.85 270 top
R191  1M/5% 1/10W  [0402]  71.12 72.39 90 top
R192  1K, DNI  [0402]  53.09 21.59 270 top
R193  1K, DNI  [0402]  49.53 24.13 270 top
R194  1K, DNI  [0402]  51.82 21.59 270 top
R195  1K/1% 1/10W  [0402]  53.09 21.59 90 bottom
R196  1K/1% 1/10W  [0402]  48.26 24.13 90 bottom
R197  1K/1% 1/10W  [0402]  51.82 21.59 90 bottom
R198  OR, DNI  [0402]  65.28 14.99 90 bottom
R199  OR, DNI  [0402]  65.28 18.03 270 bottom
R200  0E/5% 1/10W  [0402]  15.24 13.72 270 top
R201  OR, DNI  [0402]  13.97 13.72 270 top
R202  OR, DNI  [0402]  12.7 13.72 270 top
R203  2K/5% 1/10W  [0402]  17.53 8.38 180 bottom
R204  0E/5% 1/10W  [0402]  11.43 13.72 270 top
R205  0E/5% 1/10W  [0402]  7.87 9.65 0 bottom
R206  OR, DNI  [0402]  7.87 8.38 0 bottom
R207  1K, DNI  [0402]  17.53 7.11 0 bottom
R208  0E/5% 1/10W  [0402]  68.07 24.13 270 bottom
R209  OR, DNI  [0402]  69.34 24.13 270 bottom
R210  330R  [0402]  82.3 41.91 270 bottom
R211  330R  [0402]  86.36 41.91 270 bottom
R212  100K  [0402]  83.57 41.91 90 bottom
R213  100K  [0402]  85.09 41.91 270 bottom
R214  OR, DNI  [0402]  78.74 63.5 90 bottom
R215  OR, DNI  [0402]  77.47 63.5 90 bottom
R216  OR, DNI  [0402]  71.12 63.5 90 bottom
R217  OR, DNI  [0402]  78.74 76.2 90 bottom
R218  OR, DNI  [0402]  73.66 63.5 90 bottom
R219  OR, DNI  [0402]  72.39 63.5 90 bottom
R220  10K  [0402]  6.1 20.83 90 bottom
R221  10K  [0402]  95.76 6.35 270 bottom
R222  1K  [0402]  4.57 20.83 90 bottom
R223  1K  [0402]  97.28 6.35 270 bottom
R224  10E/1% 1/10W  [0402]  50.8 38.1 0 bottom
R225  10E/1% 1/10W  [0402]  50.8 33.02 0 bottom
R226  10E/1% 1/10W  [0402]  50.8 37.08 0 bottom
R227  10E/1% 1/10W  [0402]  48.01 36.58 0 top
R228  10E/1% 1/10W  [0402]  50.8 35.05 0 bottom
R229  10E/1% 1/10W  [0402]  48.01 35.56 0 top
R230  10E/1% 1/10W  [0402]  50.8 41.66 180 bottom
R231  10E/1% 1/10W  [0402]  50.8 42.67 180 bottom
R232  10E/1% 1/10W  [0402]  48.01 42.67 180 top
R233  10E/1% 1/10W  [0402]  48.01 43.69 180 top
R234  10E/1% 1/10W  [0402]  50.8 45.72 180 bottom
R235  10E/1% 1/10W  [0402]  48.01 45.72 180 top
R236  10E/1% 1/10W  [0402]  48.01 44.7 180 top
R237  10E/1% 1/10W  [0402]  50.8 43.69 180 bottom
R238  10E/1% 1/10W  [0402]  50.8 47.75 180 bottom
R239  10E/1% 1/10W  [0402]  50.8 44.7 180 bottom
R240  10E/1% 1/10W  [0402]  48.01 46.74 180 top
R241  10E/1% 1/10W  [0402]  50.8 48.77 180 bottom
R242  10E/1% 1/10W  [0402]  48.01 47.75 180 top
R243  10E/1% 1/10W  [0402]  50.8 46.74 180 bottom
R244  4.7K/5% 1/10W  [0402]  63.25 18.03 90 bottom
R245  4.7K/5% 1/10W  [0402]  63.25 14.99 270 bottom
R246  4.7K/5% 1/10W  [0402]  62.23 18.03 90 bottom
R247  4.7K/5% 1/10W  [0402]  62.23 14.99 270 bottom
R248  4.7K/5% 1/10W  [0402]  61.21 18.03 90 bottom
R249  4.7K/5% 1/10W  [0402]  61.21 14.99 270 bottom
R250  4.7K/5% 1/10W  [0402]  60.2 18.03 90 bottom
R251  4.7K/5% 1/10W  [0402]  60.2 14.99 270 bottom
R252  10K, DNI  [0402]  41.66 56.52 270 bottom
R253  1K/5% 1/10W  [0402]  60.96 60.96 90 bottom
R254  1K/5% 1/10W  [0402]  63.5 60.96 90 bottom
R255  1K/5% 1/10W  [0402]  66.04 60.96 90 bottom
R256  1K/5% 1/10W  [0402]  68.58 60.96 90 bottom
R257  5.6K/1%  [0402]  66.04 56.52 270 bottom
R258  5.6K/1%  [0402]  64.77 56.52 90 bottom
R259  5.6K/1%  [0402]  67.31 56.52 270 bottom
R260  5.6K/1%  [0402]  68.58 56.52 90 bottom
R261  10K, DNI  [0402]  39.62 56.52 270 bottom
R262  10K, DNI  [0402]  43.69 56.52 270 bottom
R263  10K, DNI  [0402]  37.59 56.52 270 bottom
R264  120, 1%  [0402]  61.37 28.5 270 bottom
R265  22E  [0402]  48.01 41.66 180 bottom
R266  22E  [0402]  48.01 39.62 180 bottom
R267  22E  [0402]  48.01 42.67 180 bottom
R268  47R  [0402]  7.87 7.11 180 bottom
R269  22E/1% 1/10W  [0402]  78.74 26.67 270 top
R270  10K  [0402]  8.38 88.9 270 bottom
R271  22E/1% 1/10W  [0402]  81.28 30.48 90 top
R272  22E/1% 1/10W  [0402]  80.01 26.67 270 top
R273  75E/5%  1/10W  [0402]  51.75 8.89 270 bottom
R274  10K/1% 1/10W  [0402]  31.75 19.37 90 bottom
R275  4.7K  [0402]  77.47 66.04 270 bottom
R276  4.7K  [0402]  71.12 66.04 270 bottom
R277  4.7K  [0402]  72.39 66.04 270 bottom
R278  4.7K  [0402]  76.2 66.04 270 bottom
R279  4.7K  [0402]  74.93 66.04 270 bottom
R280  4.7K  [0402]  81.28 66.04 270 bottom
S1  B3F-1000  [SWRST4_177X256LS-1]  49.53 77.47 90 top
S2  B3F-1000  [SWRST4_177X256LS-1]  5.33 20.83 0 top
S3  B3F-1000  [SWRST4_177X256LS-1]  96.52 6.35 90 top
SW1  SW DIP-8/SM  [SWDIP16_340SMD]  59.69 56.52 0 top
TP1  TEST POINT  [TP]  19.68 83.19 0 top
TP2  TEST POINT  [TP]  42.67 73.66 0 top
TP3  TEST POINT  [TP]  6.35 73.66 0 top
TP4  TEST POINT  [TP]  42.67 63.5 0 top
TP5  TEST POINT  [TP]  71.12 21.59 0 top
TP6  TEST POINT  [TP]  3.81 73.66 0 top
TP7  TEST POINT  [TP]  71.12 24.13 0 top
TP8  TEST POINT  [TP]  22.86 66.04 0 top
TP9  TEST POINT  [TP]  25.4 66.04 0 top
TP10  TEST POINT  [TP]  56.13 21.59 0 top
TP11  TEST POINT  [TP]  31.75 29.46 0 top
TP12  TEST POINT  [TP]  48.26 18.29 0 top
TP13  TEST POINT  [TP]  34.29 29.46 0 top
TP14  TEST POINT  [TP]  48.26 20.83 0 top
TP15  TEST POINT  [TP]  48.26 15.75 0 top
TP16  TEST POINT  [TP]  27.94 35.56 0 top
TP17  TEST POINT  [TP]  25.4 35.56 0 top
TP18  TEST POINT  [TP]  86.36 68.58 0 top
TP19  bezel  [BEZEL]  8.06 7.62 90 top
TP20  bezel  [BEZEL]  17.36 7.62 90 top
U1  TPS3707-33DR  [SOIC8]  60.96 81.28 0 top
U2  NCP349MNAE  [DFN6-1P6X2]  10.79 76.2 270 top
U3  TPS650250RHBR  [QFN32_9V]  30.48 71.12 180 top
U4  TPS2087D  [SOIC16]  31.11 83.95 270 bottom
U5  TPS2068DGNR  [MSOP8_0256P_167]  22.61 83.95 0 bottom
U6  SN74AHC1G04DBVR  [DBV5]  39.24 83.95 0 bottom
U7  OMAPL138ZWT  [BGA361_W19_P8_16X16]  60.96 38.1 270 top
U8  FT232RQ  [QFN32_9V]  82.55 12.7 270 top
U9  CDCM61001RHBT  [QFN32]  57.15 66.04 0 top
U11  SN74LVC1G11DBVR  [DBV]  74.93 33.02 0 top
U12  SN74LVC2T45DCU  [DCU]  17.78 61.98 0 top
U13  THS8135PFP  [LQFP48]  16.51 49.53 90 top
U14  SN74AVC16T245DGGR  [SOP-DGG48]  38.1 56.52 0 top
U15  SN74LVC2T45DCU  [DCU]  25.4 52.07 0 top
U16  TXS0102DCUR  [DCU]  25.4 46.99 0 top
U17  K4T1G164QF-BCF8  [BGA84_R9_P8]  37.76 39.7 180 top
U18  MT29F1G08ABCHC:C  [BGA-63]  79.36 55.7 90 top
U21  TVP5147M1PFP  [PQFP80_25V]  38.1 20.32 0 top
U22  TLV320AIC3106IRGZ  [QFN48_25V]  15.24 29.21 270 top
U23  LAN8710A-EZK  [QFN32]  76.2 71.12 270 top
U24  SN74LVC2T45DCU  [DCU]  25.4 61.98 0 top
U25  TXS0102DCUR  [DCU]  21.59 61.98 0 top
U26  AES850  [LGA23_E5_P1_6P8X6P8]  12.7 7.62 180 top
U27  74LVC1G126DBV  [DBV5]  53.34 16.51 0 bottom
U28  SN74AVC1T45DBV  [DBV]  13.72 61.98 0 top
Y1  25MHz  [SM_OSC_ABM3]  55.37 72.64 270 top
Y2  FX135A-327  [XTAL2_FX135]  64.64 24.13 90 bottom
Y3  ASE-24.000MHZ-LC  [XTAL4_74X83LS_98X126SMD]  59.82 24.13 0 bottom
Y4  ECS-143-20-5P-TR  [CSM-7]  26.67 25.91 270 top
Y5  CB3LV-3I-24M5760  [OSC4_90-100SMD_130X200]  22.99 29.21 90 bottom
Y6  25MHz  [SM_OSC_ABM3]  68.58 71.12 270 top

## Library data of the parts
BH1 = BATTERY_0
C1 C2 C5 C6 C8-C14 C22 C81 C83 C178 C179 C184 C191 C199 = CAP POL: Tolerance: TOL*; User Part Number: P/N*
C3 C4 C7 C15-C21 C23-C29 C31 C32 C34-C44 C46 C47 C50-C62 C64-C68 C70-C79 C82 C84-C86 C90-C116 C118-C122 C125-C130 C132-C143 C146-C169 C172-C177 C181-C183 C185-C190 C193 C194 C196 C197 C202-C214 = CAPACITOR NON-POL
C30 C33 C45 C48 C49 C63 C69 C80 C123 C124 C131 C170 C171 = CAPACITOR NON-POL: Tolerance: TOL*; User Part Number: P/N*
C144 C145 = CAP NP
C180 = CAP NP_1
C198 C215-C217 = CAP_0402_0.1uf_X5R_10V
C200 C201 = CAPACITOR
D1 = DIODE ZENER_1
D2 = LED_4: User Part Number: X; Tolerance: X
D3 = LED_5: User Part Number: X; Tolerance: X
D4 = LED_6: User Part Number: X; Tolerance: X
D5 = LED_7: User Part Number: X; Tolerance: X
D6 = LED_2: User Part Number: X; Tolerance: X
D7 = LED_3: User Part Number: X; Tolerance: X
D8 = TRANZORB
DN1 DN2 = DIODE_DUAL_RS_AJK_1
FB1-FB6 FB8-FB11 FB14-FB16 FB18 L4-L6 = INDUCTOR: Tolerance: TOL*; User Part Number: P/N*
J1 = Conn_PwrJack_RAPC712
J2 J3 = MINI-USB-AB-SOCKET_2
J4 = microSD_CONN_8: User Part Number: X; Tolerance: X
J5 = CONN_54819-0578_2: User Part Number: PART#; Tolerance: TOL
J6 = CON14AP_1
J7 = 8 HEADER_0
J8 = CONN ASY CENT S/S 14_1
J9 = CONNECTOR COAX-J_1
J10 = SJD-3510-33
J11 = Kycon ST-3500_3
J13 = DUALUSB_ETHER_0
J14 J15 = CONN PCB 20x2-S_0
J16 = CONN FLEX 36_0
JP1 = B2S_1
JP2-JP4 = Header_2x1
L1-L3 = INDUCTOR IRON
P1 P2 = HEADER_10X2_0
Q1-Q4 = 2N1613_1
Q5 Q6 = RN1907
R1 R29 R81 R94 R95 R107-R112 R115 R116 R120 R121 R126-R136 R138 R140 R164 R176 R181 R186 R192-R199 R210-R219 R224-R243 R252 R261-R263 R269 R271 R272 = RESISTOR
R2 R4 R5 = 0.05ohm0.5W1%Sense1206: Tolerance: TOL*; User Part Number: P/N*
R3 R6-R10 R16 R22-R28 R30 R43 R45 R46 R48 R50-R55 R57-R67 R73-R80 R82-R93 R96-R106 R113 R114 R117-R119 R122-R125 R137 R139 R141-R163 R165-R175 R177-R179 R182-R185 R187-R191 R200-R209 R220-R223 R244-R251 R253-R260 R264-R268 R270 R273-R280 = R
R11-R15 R17-R21 R31 R33-R41 R44 R47 R49 = R: signal model: 33OHMRESISTOR1_16W5_0402_SM_735_33
R42 = RESISTOR: signal model: 33OHMRESISTOR1_16W5_0402_SM_735_33
R180 = RES_0.1_0805: Tolerance: TOL*; User Part Number: P/N*
S1-S3 = SW_KT11P2JM_4
SW1 = SW DIP-8/SM
TP1-TP18 = TEST POINT
TP19 TP20 = T POINT A
U1 = TPS3705_0
U2 = IC_MCP349_0: Tolerance: X; User Part Number: X
U3 = TPS650250_3
U4 = TPS2087B: Tolerance: ***; User Part Number: ***
U5 = TPS2087_1
U6 = NC7SZ14P5X_2
U7 = OMAP-L138_0: Tolerance: TOL*; User Part Number: PRT#
U8 = FT232RQ_1
U9 = CDCM61001RHBT_0
U11 = SN74LVC1G11
U12 U15 U24 = SN74LVC2T45DCUT
U13 = THS8135PHP_8
U14 = OCT_DS_BUSTRASCEIVER_0
U16 U25 = TXS0102DCUR
U17 = MT47H64M16HR _1: Tolerance: TOL*; User Part Number: PRT#
U18 = K9f1208R0C_9
U21 = TVP5146M2_1
U22 = TLV320AIC3106_5
U23 = LAN8700_small_0
U26 = AES850_0: Tolerance: TOL*; User Part Number: PRT#
U27 = 74LVC1G126DBV_0
U28 = SN74AVC1T45DBV
Y1 Y6 = Crystal25MHzABM3
Y2 = QUARTZ-32KHz-CM200S_0: tolerance: 20ppm
Y3 = ASEM4-24_0.000MHZ-LR
Y4 = CRYSTAL_5
Y5 = OSC4/SM_0: Tolerance: TOL*; User Part Number: P/N*

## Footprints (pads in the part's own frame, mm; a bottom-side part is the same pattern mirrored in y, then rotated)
0402
  rect 0.635x0.508 smd: 1(-0.508,0) 2(0.508,0)
0603
  rect 0.889x0.813 smd: 1(-0.762,0) 2(0.762,0)
0805
  rect 1.27x1.524 smd: 1(-0.953,0) 2(0.953,0)
1206_4PIN
  rect 1.753x1.092 smd: 1(-1.372,-0.8) 2(1.397,-0.826) 3(-1.372,0.8) 4(1.397,0.775)
1210
  rect 1.6x2.667 smd: 1(-1.397,0) 2(1.397,0)
BATTERY
  round 1.905 hole 1.143: 1(-3.4,0) 2(3.4,0)
BEZEL
  rect 4.597x1.295 smd: 1(0,0)
BGA84_R9_P8
  round 1.016 smd: (4.401,8.001) (4.401,-8.001)
  round 0.356 smd: A1(-3.2,5.6) A2(-2.4,5.6) A3(-1.6,5.6) A7(1.6,5.6) A8(2.4,5.6) A9(3.2,5.6) B1(-3.2,4.8) B2(-2.4,4.8) B3(-1.6,4.8) B7(1.6,4.8) B8(2.4,4.8) B9(3.2,4.8) C1(-3.2,4) C2(-2.4,4) C3(-1.6,4) C7(1.6,4) C8(2.4,4) C9(3.2,4) D1(-3.2,3.2) D2(-2.4,3.2) D3(-1.6,3.2) D7(1.6,3.2) D8(2.4,3.2) D9(3.2,3.2) E1(-3.2,2.4) E2(-2.4,2.4) E3(-1.6,2.4) E7(1.6,2.4) E8(2.4,2.4) E9(3.2,2.4) F1(-3.2,1.6) F2(-2.4,1.6) F3(-1.6,1.6) F7(1.6,1.6) F8(2.4,1.6) F9(3.2,1.6) G1(-3.2,0.8) G2(-2.4,0.8) G3(-1.6,0.8) G7(1.6,0.8) G8(2.4,0.8) G9(3.2,0.8) H1(-3.2,0) H2(-2.4,0) H3(-1.6,0) H7(1.6,0) H8(2.4,0) H9(3.2,0) J1(-3.2,-0.8) J2(-2.4,-0.8) J3(-1.6,-0.8) J7(1.6,-0.8) J8(2.4,-0.8) J9(3.2,-0.8) K2(-2.4,-1.6) K3(-1.6,-1.6) K7(1.6,-1.6) K8(2.4,-1.6) K9(3.2,-1.6) L1(-3.2,-2.4) L2(-2.4,-2.4) L3(-1.6,-2.4) L7(1.6,-2.4) L8(2.4,-2.4) M2(-2.4,-3.2) M3(-1.6,-3.2) M7(1.6,-3.2) M8(2.4,-3.2) M9(3.2,-3.2) N1(-3.2,-4) N2(-2.4,-4) N3(-1.6,-4) N7(1.6,-4) N8(2.4,-4) P2(-2.4,-4.8) P3(-1.6,-4.8) P7(1.6,-4.8) P8(2.4,-4.8) P9(3.2,-4.8) R1(-3.2,-5.6) R2(-2.4,-5.6) R3(-1.6,-5.6) R7(1.6,-5.6) R8(2.4,-5.6)
BGA361_W19_P8_16X16
  round 0.356 smd: A1(-7.2,7.2) A2(-6.4,7.2) A3(-5.6,7.2) A4(-4.8,7.2) A5(-4,7.2) A6(-3.2,7.2) A7(-2.4,7.2) A8(-1.6,7.2) A9(-0.8,7.2) A10(0,7.2) A11(0.8,7.2) A12(1.6,7.2) A13(2.4,7.2) A14(3.2,7.2) A15(4,7.2) A16(4.8,7.2) A17(5.6,7.2) A18(6.4,7.2) A19(7.2,7.2) B1(-7.2,6.4) B2(-6.4,6.4) B3(-5.6,6.4) B4(-4.8,6.4) B5(-4,6.4) B6(-3.2,6.4) B7(-2.4,6.4) B8(-1.6,6.4) B9(-0.8,6.4) B10(0,6.4) B11(0.8,6.4) B12(1.6,6.4) B13(2.4,6.4) B14(3.2,6.4) B15(4,6.4) B16(4.8,6.4) B17(5.6,6.4) B18(6.4,6.4) B19(7.2,6.4) C1(-7.2,5.6) C2(-6.4,5.6) C3(-5.6,5.6) C4(-4.8,5.6) C5(-4,5.6) C6(-3.2,5.6) C7(-2.4,5.6) C8(-1.6,5.6) C9(-0.8,5.6) C10(0,5.6) C11(0.8,5.6) C12(1.6,5.6) C13(2.4,5.6) C14(3.2,5.6) C15(4,5.6) C16(4.8,5.6) C17(5.6,5.6) C18(6.4,5.6) C19(7.2,5.6) D1(-7.2,4.8) D2(-6.4,4.8) D3(-5.6,4.8) D4(-4.8,4.8) D5(-4,4.8) D6(-3.2,4.8) D7(-2.4,4.8) D8(-1.6,4.8) D9(-0.8,4.8) D10(0,4.8) D11(0.8,4.8) D12(1.6,4.8) D13(2.4,4.8) D14(3.2,4.8) D15(4,4.8) D16(4.8,4.8) D17(5.6,4.8) D18(6.4,4.8) D19(7.2,4.8) E1(-7.2,4) E2(-6.4,4) E3(-5.6,4) E4(-4.8,4) E5(-4,4) E6(-3.2,4) E7(-2.4,4) E8(-1.6,4) E9(-0.8,4) E10(0,4) E11(0.8,4) E12(1.6,4) E13(2.4,4) E14(3.2,4) E15(4,4) E16(4.8,4) E17(5.6,4) E18(6.4,4) E19(7.2,4) F1(-7.2,3.2) F2(-6.4,3.2) F3(-5.6,3.2) F4(-4.8,3.2) F5(-4,3.2) F6(-3.2,3.2) F7(-2.4,3.2) F8(-1.6,3.2) F9(-0.8,3.2) F10(0,3.2) F11(0.8,3.2) F12(1.6,3.2) F13(2.4,3.2) F14(3.2,3.2) F15(4,3.2) F16(4.8,3.2) F17(5.6,3.2) F18(6.4,3.2) F19(7.2,3.2) G1(-7.2,2.4) G2(-6.4,2.4) G3(-5.6,2.4) G4(-4.8,2.4) G5(-4,2.4) G6(-3.2,2.4) G7(-2.4,2.4) G8(-1.6,2.4) G9(-0.8,2.4) G10(0,2.4) G11(0.8,2.4) G12(1.6,2.4) G13(2.4,2.4) G14(3.2,2.4) G15(4,2.4) G16(4.8,2.4) G17(5.6,2.4) G18(6.4,2.4) G19(7.2,2.4) H1(-7.2,1.6) H2(-6.4,1.6) H3(-5.6,1.6) H4(-4.8,1.6) H5(-4,1.6) H6(-3.2,1.6) H7(-2.4,1.6) H8(-1.6,1.6) H9(-0.8,1.6) H10(0,1.6) H11(0.8,1.6) H12(1.6,1.6) H13(2.4,1.6) H14(3.2,1.6) H15(4,1.6) H16(4.8,1.6) H17(5.6,1.6) H18(6.4,1.6) H19(7.2,1.6) J1(-7.2,0.8) J2(-6.4,0.8) J3(-5.6,0.8) J4(-4.8,0.8) J5(-4,0.8) J6(-3.2,0.8) J7(-2.4,0.8) J8(-1.6,0.8) J9(-0.8,0.8) J10(0,0.8) J11(0.8,0.8) J12(1.6,0.8) J13(2.4,0.8) J14(3.2,0.8) J15(4,0.8) J16(4.8,0.8) J17(5.6,0.8) J18(6.4,0.8) J19(7.2,0.8) K1(-7.2,0) K2(-6.4,0) K3(-5.6,0) K4(-4.8,0) K5(-4,0) K6(-3.2,0) K7(-2.4,0) K8(-1.6,0) K9(-0.8,0) K10(0,0) K11(0.8,0) K12(1.6,0) K13(2.4,0) K14(3.2,0) K15(4,0) K16(4.8,0) K17(5.6,0) K18(6.4,0) K19(7.2,0) L1(-7.2,-0.8) L2(-6.4,-0.8) L3(-5.6,-0.8) L4(-4.8,-0.8) L5(-4,-0.8) L6(-3.2,-0.8) L7(-2.4,-0.8) L8(-1.6,-0.8) L9(-0.8,-0.8) L10(0,-0.8) L11(0.8,-0.8) L12(1.6,-0.8) L13(2.4,-0.8) L14(3.2,-0.8) L15(4,-0.8) L16(4.8,-0.8) L17(5.6,-0.8) L18(6.4,-0.8) L19(7.2,-0.8) M1(-7.2,-1.6) M2(-6.4,-1.6) M3(-5.6,-1.6) M4(-4.8,-1.6) M5(-4,-1.6) M6(-3.2,-1.6) M7(-2.4,-1.6) M8(-1.6,-1.6) M9(-0.8,-1.6) M10(0,-1.6) M11(0.8,-1.6) M12(1.6,-1.6) M13(2.4,-1.6) M14(3.2,-1.6) M15(4,-1.6) M16(4.8,-1.6) M17(5.6,-1.6) M18(6.4,-1.6) M19(7.2,-1.6) N1(-7.2,-2.4) N2(-6.4,-2.4) N3(-5.6,-2.4) N4(-4.8,-2.4) N5(-4,-2.4) N6(-3.2,-2.4) N7(-2.4,-2.4) N8(-1.6,-2.4) N9(-0.8,-2.4) N10(0,-2.4) N11(0.8,-2.4) N12(1.6,-2.4) N13(2.4,-2.4) N14(3.2,-2.4) N15(4,-2.4) N16(4.8,-2.4) N17(5.6,-2.4) N18(6.4,-2.4) N19(7.2,-2.4) P1(-7.2,-3.2) P2(-6.4,-3.2) P3(-5.6,-3.2) P4(-4.8,-3.2) P5(-4,-3.2) P6(-3.2,-3.2) P7(-2.4,-3.2) P8(-1.6,-3.2) P9(-0.8,-3.2) P10(0,-3.2) P11(0.8,-3.2) P12(1.6,-3.2) P13(2.4,-3.2) P14(3.2,-3.2) P15(4,-3.2) P16(4.8,-3.2) P17(5.6,-3.2) P18(6.4,-3.2) P19(7.2,-3.2) R1(-7.2,-4) R2(-6.4,-4) R3(-5.6,-4) R4(-4.8,-4) R5(-4,-4) R6(-3.2,-4) R7(-2.4,-4) R8(-1.6,-4) R9(-0.8,-4) R10(0,-4) R11(0.8,-4) R12(1.6,-4) R13(2.4,-4) R14(3.2,-4) R15(4,-4) R16(4.8,-4) R17(5.6,-4) R18(6.4,-4) R19(7.2,-4) T1(-7.2,-4.8) T2(-6.4,-4.8) T3(-5.6,-4.8) T4(-4.8,-4.8) T5(-4,-4.8) T6(-3.2,-4.8) T7(-2.4,-4.8) T8(-1.6,-4.8) T9(-0.8,-4.8) T10(0,-4.8) T11(0.8,-4.8) T12(1.6,-4.8) T13(2.4,-4.8) T14(3.2,-4.8) T15(4,-4.8) T16(4.8,-4.8) T17(5.6,-4.8) T18(6.4,-4.8) T19(7.2,-4.8) U1(-7.2,-5.6) U2(-6.4,-5.6) U3(-5.6,-5.6) U4(-4.8,-5.6) U5(-4,-5.6) U6(-3.2,-5.6) U7(-2.4,-5.6) U8(-1.6,-5.6) U9(-0.8,-5.6) U10(0,-5.6) U11(0.8,-5.6) U12(1.6,-5.6) U13(2.4,-5.6) U14(3.2,-5.6) U15(4,-5.6) U16(4.8,-5.6) U17(5.6,-5.6) U18(6.4,-5.6) U19(7.2,-5.6) V1(-7.2,-6.4) V2(-6.4,-6.4) V3(-5.6,-6.4) V4(-4.8,-6.4) V5(-4,-6.4) V6(-3.2,-6.4) V7(-2.4,-6.4) V8(-1.6,-6.4) V9(-0.8,-6.4) V10(0,-6.4) V11(0.8,-6.4) V12(1.6,-6.4) V13(2.4,-6.4) V14(3.2,-6.4) V15(4,-6.4) V16(4.8,-6.4) V17(5.6,-6.4) V18(6.4,-6.4) V19(7.2,-6.4) W1(-7.2,-7.2) W2(-6.4,-7.2) W3(-5.6,-7.2) W4(-4.8,-7.2) W5(-4,-7.2) W6(-3.2,-7.2) W7(-2.4,-7.2) W8(-1.6,-7.2) W9(-0.8,-7.2) W10(0,-7.2) W11(0.8,-7.2) W12(1.6,-7.2) W13(2.4,-7.2) W14(3.2,-7.2) W15(4,-7.2) W16(4.8,-7.2) W17(5.6,-7.2) W18(6.4,-7.2) W19(7.2,-7.2)
BGA-63
  round 1.016 smd: (-7.601,-6.801) (7.601,6.801)
  round 0.406 smd: A1(-4.4,-3.6) A2(-4.4,-2.8) A9(-4.4,2.8) A10(-4.4,3.6) B1(-3.6,-3.6) B9(-3.6,2.8) B10(-3.6,3.6) C3(-2.8,-2) C4(-2.8,-1.2) C5(-2.8,-0.4) C6(-2.8,0.4) C7(-2.8,1.2) C8(-2.8,2) D3(-2,-2) D4(-2,-1.2) D5(-2,-0.4) D6(-2,0.4) D7(-2,1.2) D8(-2,2) E3(-1.2,-2) E4(-1.2,-1.2) E5(-1.2,-0.4) E6(-1.2,0.4) E7(-1.2,1.2) E8(-1.2,2) F3(-0.4,-2) F4(-0.4,-1.2) F5(-0.4,-0.4) F6(-0.4,0.4) F7(-0.4,1.2) F8(-0.4,2) G3(0.4,-2) G4(0.4,-1.2) G5(0.4,-0.4) G6(0.4,0.4) G7(0.4,1.2) G8(0.4,2) H3(1.2,-2) H4(1.2,-1.2) H5(1.2,-0.4) H6(1.2,0.4) H7(1.2,1.2) H8(1.2,2) J3(2,-2) J4(2,-1.2) J5(2,-0.4) J6(2,0.4) J7(2,1.2) J8(2,2) K3(2.8,-2) K4(2.8,-1.2) K5(2.8,-0.4) K6(2.8,0.4) K7(2.8,1.2) K8(2.8,2) L1(3.6,-3.6) L2(3.6,-2.8) L9(3.6,2.8) L10(3.6,3.6) M1(4.4,-3.6) M2(4.4,-2.8) M9(4.4,2.8) M10(4.4,3.6)
CON2X100P-14_V6
  rect 1.524x1.524 hole 1.016: 1(-7.62,-1.27)
  round 1.524 hole 1.016: 2(-7.62,1.27) 3(-5.08,-1.27) 4(-5.08,1.27) 5(-2.54,-1.27) 7(0,-1.27) 8(0,1.27) 9(2.54,-1.27) 10(2.54,1.27) 11(5.08,-1.27) 12(5.08,1.27) 13(7.62,-1.27) 14(7.62,1.27)
CON36UPSMD_P5MM
  rect 0.6x1.5 smd: 1(8.75,1.4) 2(8.25,-1.4) 3(7.75,1.4) 4(7.25,-1.4) 5(6.75,1.4) 6(6.25,-1.4) 7(5.75,1.4) 8(5.25,-1.4) 9(4.75,1.4) 10(4.25,-1.4) 11(3.75,1.4) 12(3.25,-1.4) 13(2.75,1.4) 14(2.25,-1.4) 15(1.75,1.4) 16(1.25,-1.4) 17(0.75,1.4) 18(0.25,-1.4) 19(-0.25,1.4) 20(-0.75,-1.4) 21(-1.25,1.4) 22(-1.75,-1.4) 23(-2.25,1.4) 24(-2.75,-1.4) 25(-3.25,1.4) 26(-3.75,-1.4) 27(-4.25,1.4) 28(-4.75,-1.4) 29(-5.25,1.4) 30(-5.75,-1.4) 31(-6.25,1.4) 32(-6.75,-1.4) 33(-7.25,1.4) 34(-7.75,-1.4) 35(-8.25,1.4) 36(-8.75,-1.4)
  rect 0.8x1.5 smd: 37(9.75,-1.4) 38(9.75,1.4) 39(-9.75,-1.4) 40(-9.75,1.4)
CONN2X10_4028
  round 1.016 hole 0.711: 1(0,0) 2(0,1.27) 3(1.27,0) 4(1.27,1.27) 5(2.54,0) 6(2.54,1.27) 7(3.81,0) 8(3.81,1.27) 9(5.08,0) 10(5.08,1.27) 11(6.35,0) 12(6.35,1.27) 13(7.62,0) 14(7.62,1.27) 15(8.89,0) 16(8.89,1.27) 17(10.16,0) 18(10.16,1.27) 19(11.43,0) 20(11.43,1.27)
CSM-7
  rect 5.588x2.032 smd: 1(-4.75,0) 2(4.75,0)
DB15F_60-59LS
  round 1.956 hole 1.956 unplated: (-9.525,0) (9.525,0)
  round 1.143 hole 0.711: 1(-3.81,0.508) 2(-1.524,-0.991) 3(0.762,0.508) 4(3.048,-0.991) 5(5.334,0.508) 6(-5.334,0.508) 7(-3.048,-0.991) 8(-0.762,0.508) 9(1.524,-0.991) 10(3.81,0.508) 11(-4.572,-0.991) 12(-2.286,0.508) 13(0,-0.991) 14(2.286,0.508) 15(4.572,-0.991)
  round 2.54 hole 1.93: 16(-15.367,-3.302) 17(15.367,-3.302)
DBV
  rect 0.635x1.27 smd: 1(-0.95,-1.25) 2(0,-1.25) 3(0.95,-1.25) 4(0.95,1.25) 5(0,1.25) 6(-0.95,1.25)
DBV5
  rect 0.635x1.27 smd: 1(-0.95,-1.25) 2(0,-1.25) 3(0.95,-1.25) 4(0.95,1.25) 5(-0.95,1.25)
DCU
  rect 0.254x1.143 smd: 1(-0.75,-1.475) 2(-0.25,-1.475) 3(0.25,-1.475) 4(0.75,-1.475) 5(0.75,1.475) 6(0.25,1.475) 7(-0.25,1.475) 8(-0.75,1.475)
DFN6-1P6X2
  rect 0.356x0.457 smd: 1(-0.5,-0.94) 2(0,-0.94) 3(0.5,-0.94) 4(0.5,0.94) 5(0,0.94) 6(-0.5,0.94)
  rect 1.143x1.143 smd: 7(0,0)
DO1006
  rect 0.559x0.61 smd: 1(-0.419,0) 2(0.419,0)
HEADER23X2
  rect 1.524x1.524 hole 1.016: 1(0,0)
  round 1.524 hole 1.016: 2(0,2.54) 3(2.54,0) 4(2.54,2.54) 5(5.08,0) 6(5.08,2.54) 7(7.62,0) 8(7.62,2.54) 9(10.16,0) 10(10.16,2.54) 11(12.7,0) 12(12.7,2.54) 13(15.24,0) 14(15.24,2.54) 15(17.78,0) 16(17.78,2.54) 17(20.32,0) 18(20.32,2.54) 19(22.86,0) 20(22.86,2.54) 21(25.4,0) 22(25.4,2.54) 23(27.94,0) 24(27.94,2.54) 25(30.48,0) 26(30.48,2.54) 27(33.02,0) 28(33.02,2.54) 29(35.56,0) 30(35.56,2.54) 31(38.1,0) 32(38.1,2.54) 33(40.64,0) 34(40.64,2.54) 35(43.18,0) 36(43.18,2.54) 37(45.72,0) 38(45.72,2.54) 39(48.26,0) 40(48.26,2.54) 41(50.8,0) 42(50.8,2.54) 43(53.34,0) 44(53.34,2.54) 45(55.88,0) 46(55.88,2.54)
HEADER_2X1
  rect 1.778x1.778 hole 1.016: 1(0,0)
  round 1.778 hole 1.016: 2(0,2.54)
IND3P4SMD_5SQ
  custom 0.525x0.525 smd: 1(-1.7,0) 2(1.7,0)
JACK6_551X433_STACK
  rect 2x2.2 hole 2x2.2 unplated: (-2,0) (2,0)
  round 2.159 hole 1.499: 1(-5,0) 2(-6.25,-7.5) 3(6.25,-7.5) 4(5,0) 5(5,-5) 6(-5,-5)
LED2-31SQ
  rect 0.787x0.787 smd: 1(-0.749,0) 2(0.749,0)
LGA23_E5_P1_6P8X6P8
  rect 0.508x0.508 smd: A2(-1,2) A3(0,2) A4(1,2) A5(2,2) B1(-2,1) B2(-1,1) B3(0,1) B4(1,1) B5(2,1) C1(-2,0) C2(-1,0) C4(1,0) C5(2,0) D1(-2,-1) D2(-1,-1) D3(0,-1) D4(1,-1) D5(2,-1) E1(-2,-2) E2(-1,-2) E3(0,-2) E4(1,-2) E5(2,-2)
LQFP48
  rect 0.254x1.651 smd: 1(-2.75,-4.1) 2(-2.25,-4.1) 3(-1.75,-4.1) 4(-1.25,-4.1) 5(-0.75,-4.1) 6(-0.25,-4.1) 7(0.25,-4.1) 8(0.75,-4.1) 9(1.25,-4.1) 10(1.75,-4.1) 11(2.25,-4.1) 12(2.75,-4.1) 25(2.75,4.1) 26(2.25,4.1) 27(1.75,4.1) 28(1.25,4.1) 29(0.75,4.1) 30(0.25,4.1) 31(-0.25,4.1) 32(-0.75,4.1) 33(-1.25,4.1) 34(-1.75,4.1) 35(-2.25,4.1) 36(-2.75,4.1)
  rect 1.651x0.254 smd: 13(4.1,-2.75) 14(4.1,-2.25) 15(4.1,-1.75) 16(4.1,-1.25) 17(4.1,-0.75) 18(4.1,-0.25) 19(4.1,0.25) 20(4.1,0.75) 21(4.1,1.25) 22(4.1,1.75) 23(4.1,2.25) 24(4.1,2.75) 37(-4.1,2.75) 38(-4.1,2.25) 39(-4.1,1.75) 40(-4.1,1.25) 41(-4.1,0.75) 42(-4.1,0.25) 43(-4.1,-0.25) 44(-4.1,-0.75) 45(-4.1,-1.25) 46(-4.1,-1.75) 47(-4.1,-2.25) 48(-4.1,-2.75)
  rect 3.861x3.861 smd: 49(0,0)
MSOP8_0256P_167
  rect 0.355x1.549 smd: 1(-0.975,-2.12) 2(-0.325,-2.12) 3(0.325,-2.12) 4(0.975,-2.12) 5(0.975,2.12) 6(0.325,2.12) 7(-0.325,2.12) 8(-0.975,2.12)
  rect 1.905x1.575 smd: 9(0,0)
OSC4_90-100SMD_130X200
  rect 1.6x1.524 smd: 1(-1.27,-1.143) 2(1.27,-1.143) 3(1.27,1.143) 4(-1.27,1.143)
PQFP80_25V
  rect 0.254x1.651 smd: 1(-4.75,-6.6) 2(-4.25,-6.6) 3(-3.75,-6.6) 4(-3.25,-6.6) 5(-2.75,-6.6) 6(-2.25,-6.6) 7(-1.75,-6.6) 8(-1.25,-6.6) 9(-0.75,-6.6) 10(-0.25,-6.6) 11(0.25,-6.6) 12(0.75,-6.6) 13(1.25,-6.6) 14(1.75,-6.6) 15(2.25,-6.6) 16(2.75,-6.6) 17(3.25,-6.6) 18(3.75,-6.6) 19(4.25,-6.6) 20(4.75,-6.6) 41(4.75,6.6) 42(4.25,6.6) 43(3.75,6.6) 44(3.25,6.6) 45(2.75,6.6) 46(2.25,6.6) 47(1.75,6.6) 48(1.25,6.6) 49(0.75,6.6) 50(0.25,6.6) 51(-0.25,6.6) 52(-0.75,6.6) 53(-1.25,6.6) 54(-1.75,6.6) 55(-2.25,6.6) 56(-2.75,6.6) 57(-3.25,6.6) 58(-3.75,6.6) 59(-4.25,6.6) 60(-4.75,6.6)
  rect 1.651x0.254 smd: 21(6.6,-4.75) 22(6.6,-4.25) 23(6.6,-3.75) 24(6.6,-3.25) 25(6.6,-2.75) 26(6.6,-2.25) 27(6.6,-1.75) 28(6.6,-1.25) 29(6.6,-0.75) 30(6.6,-0.25) 31(6.6,0.25) 32(6.6,0.75) 33(6.6,1.25) 34(6.6,1.75) 35(6.6,2.25) 36(6.6,2.75) 37(6.6,3.25) 38(6.6,3.75) 39(6.6,4.25) 40(6.6,4.75) 61(-6.6,4.75) 62(-6.6,4.25) 63(-6.6,3.75) 64(-6.6,3.25) 65(-6.6,2.75) 66(-6.6,2.25) 67(-6.6,1.75) 68(-6.6,1.25) 69(-6.6,0.75) 70(-6.6,0.25) 71(-6.6,-0.25) 72(-6.6,-0.75) 73(-6.6,-1.25) 74(-6.6,-1.75) 75(-6.6,-2.25) 76(-6.6,-2.75) 77(-6.6,-3.25) 78(-6.6,-3.75) 79(-6.6,-4.25) 80(-6.6,-4.75)
  rect 6.223x6.223 smd: 81(0,0)
QFN32
  custom 0.058x0.058 smd: 1(-1.75,-2.475) 2(-1.25,-2.475) 3(-0.75,-2.475) 4(-0.25,-2.475) 5(0.25,-2.475) 6(0.75,-2.475) 7(1.25,-2.475) 8(1.75,-2.475) 9(2.475,-1.75) 10(2.475,-1.25) 11(2.475,-0.75) 12(2.475,-0.25) 13(2.475,0.25) 14(2.475,0.75) 15(2.475,1.25) 16(2.475,1.75) 17(1.75,2.475) 18(1.25,2.475) 19(0.75,2.475) 20(0.25,2.475) 21(-0.25,2.475) 22(-0.75,2.475) 23(-1.25,2.475) 24(-1.75,2.475) 25(-2.475,1.75) 26(-2.475,1.25) 27(-2.475,0.75) 28(-2.475,0.25) 29(-2.475,-0.25) 30(-2.475,-0.75) 31(-2.475,-1.25) 32(-2.475,-1.75)
  rect 3.454x3.454 smd: 33(0,0)
QFN32_9V
  custom 0.058x0.058 smd: 1(-1.75,-2.475) 2(-1.25,-2.475) 3(-0.75,-2.475) 4(-0.25,-2.475) 5(0.25,-2.475) 6(0.75,-2.475) 7(1.25,-2.475) 8(1.75,-2.475) 9(2.475,-1.75) 10(2.475,-1.25) 11(2.475,-0.75) 12(2.475,-0.25) 13(2.475,0.25) 14(2.475,0.75) 15(2.475,1.25) 16(2.475,1.75) 17(1.75,2.475) 18(1.25,2.475) 19(0.75,2.475) 20(0.25,2.475) 21(-0.25,2.475) 22(-0.75,2.475) 23(-1.25,2.475) 24(-1.75,2.475) 25(-2.475,1.75) 26(-2.475,1.25) 27(-2.475,0.75) 28(-2.475,0.25) 29(-2.475,-0.25) 30(-2.475,-0.75) 31(-2.475,-1.25) 32(-2.475,-1.75)
  rect 3.454x3.454 smd: 33(0,0)
